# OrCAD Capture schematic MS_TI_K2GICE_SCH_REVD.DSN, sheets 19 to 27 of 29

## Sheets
19 P19_K2G_ICE_LCD_JTAG: size C; title: OLED_JTAG
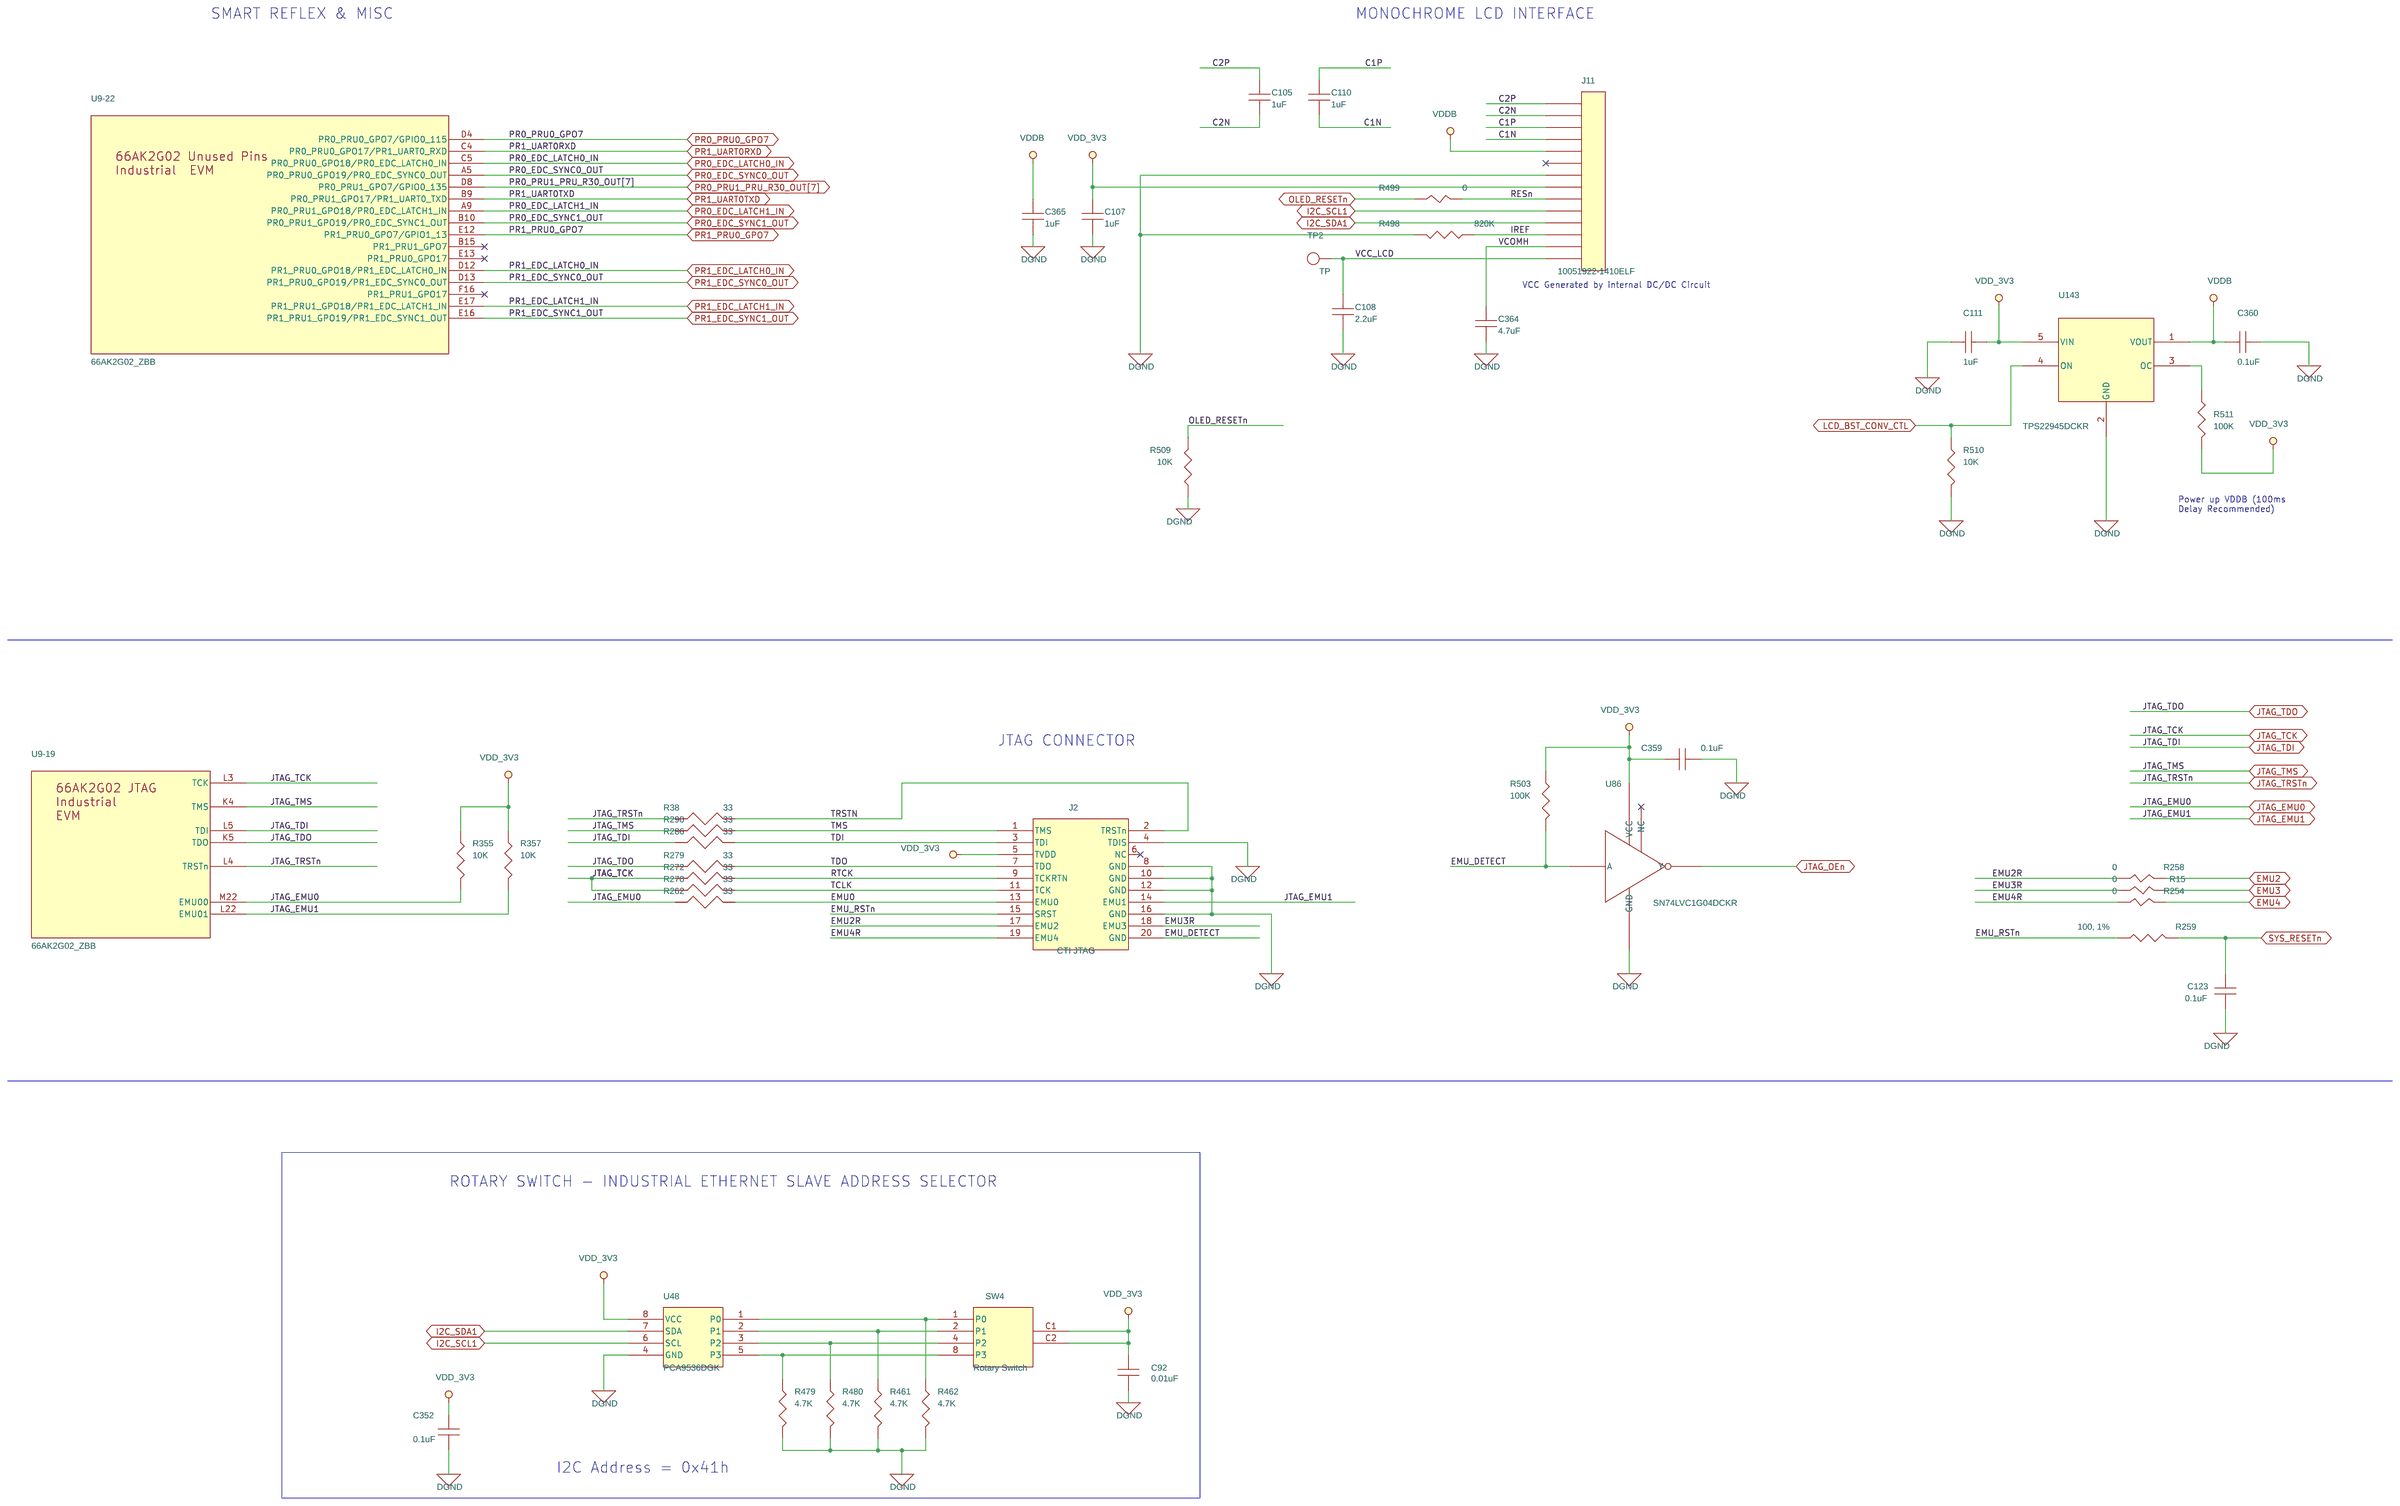
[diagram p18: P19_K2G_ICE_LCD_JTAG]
20 P20_K2G_ICE_INDUSTRIAL_LEDS: size C; title: INDUSTRIAL_LEDS
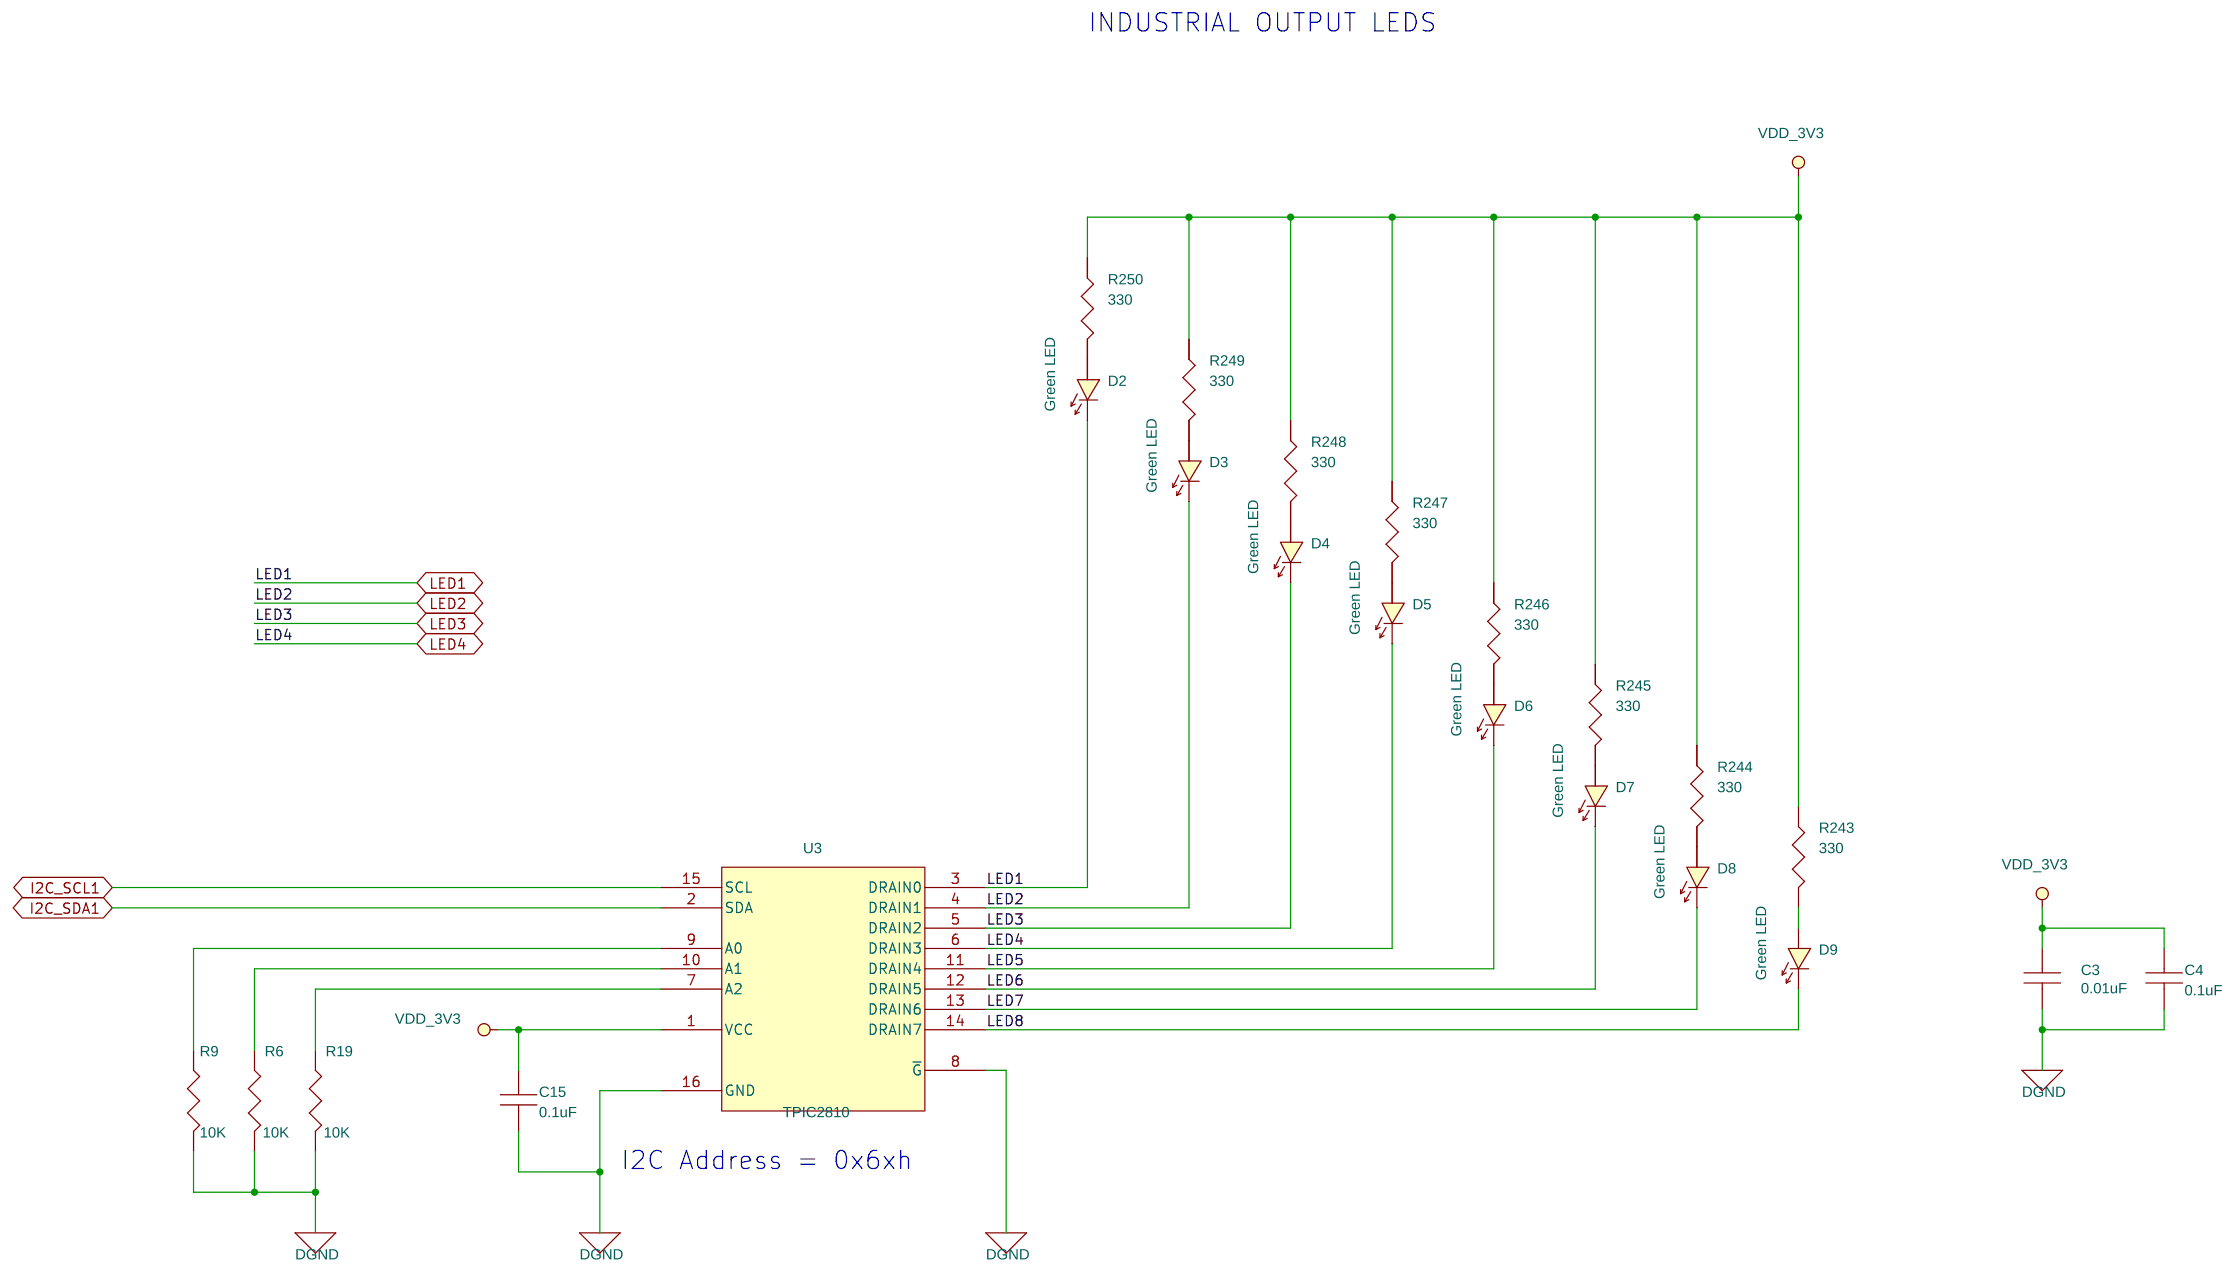
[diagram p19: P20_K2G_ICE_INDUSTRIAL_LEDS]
21 P21_USB JTAG: size C; title: USB JTAG
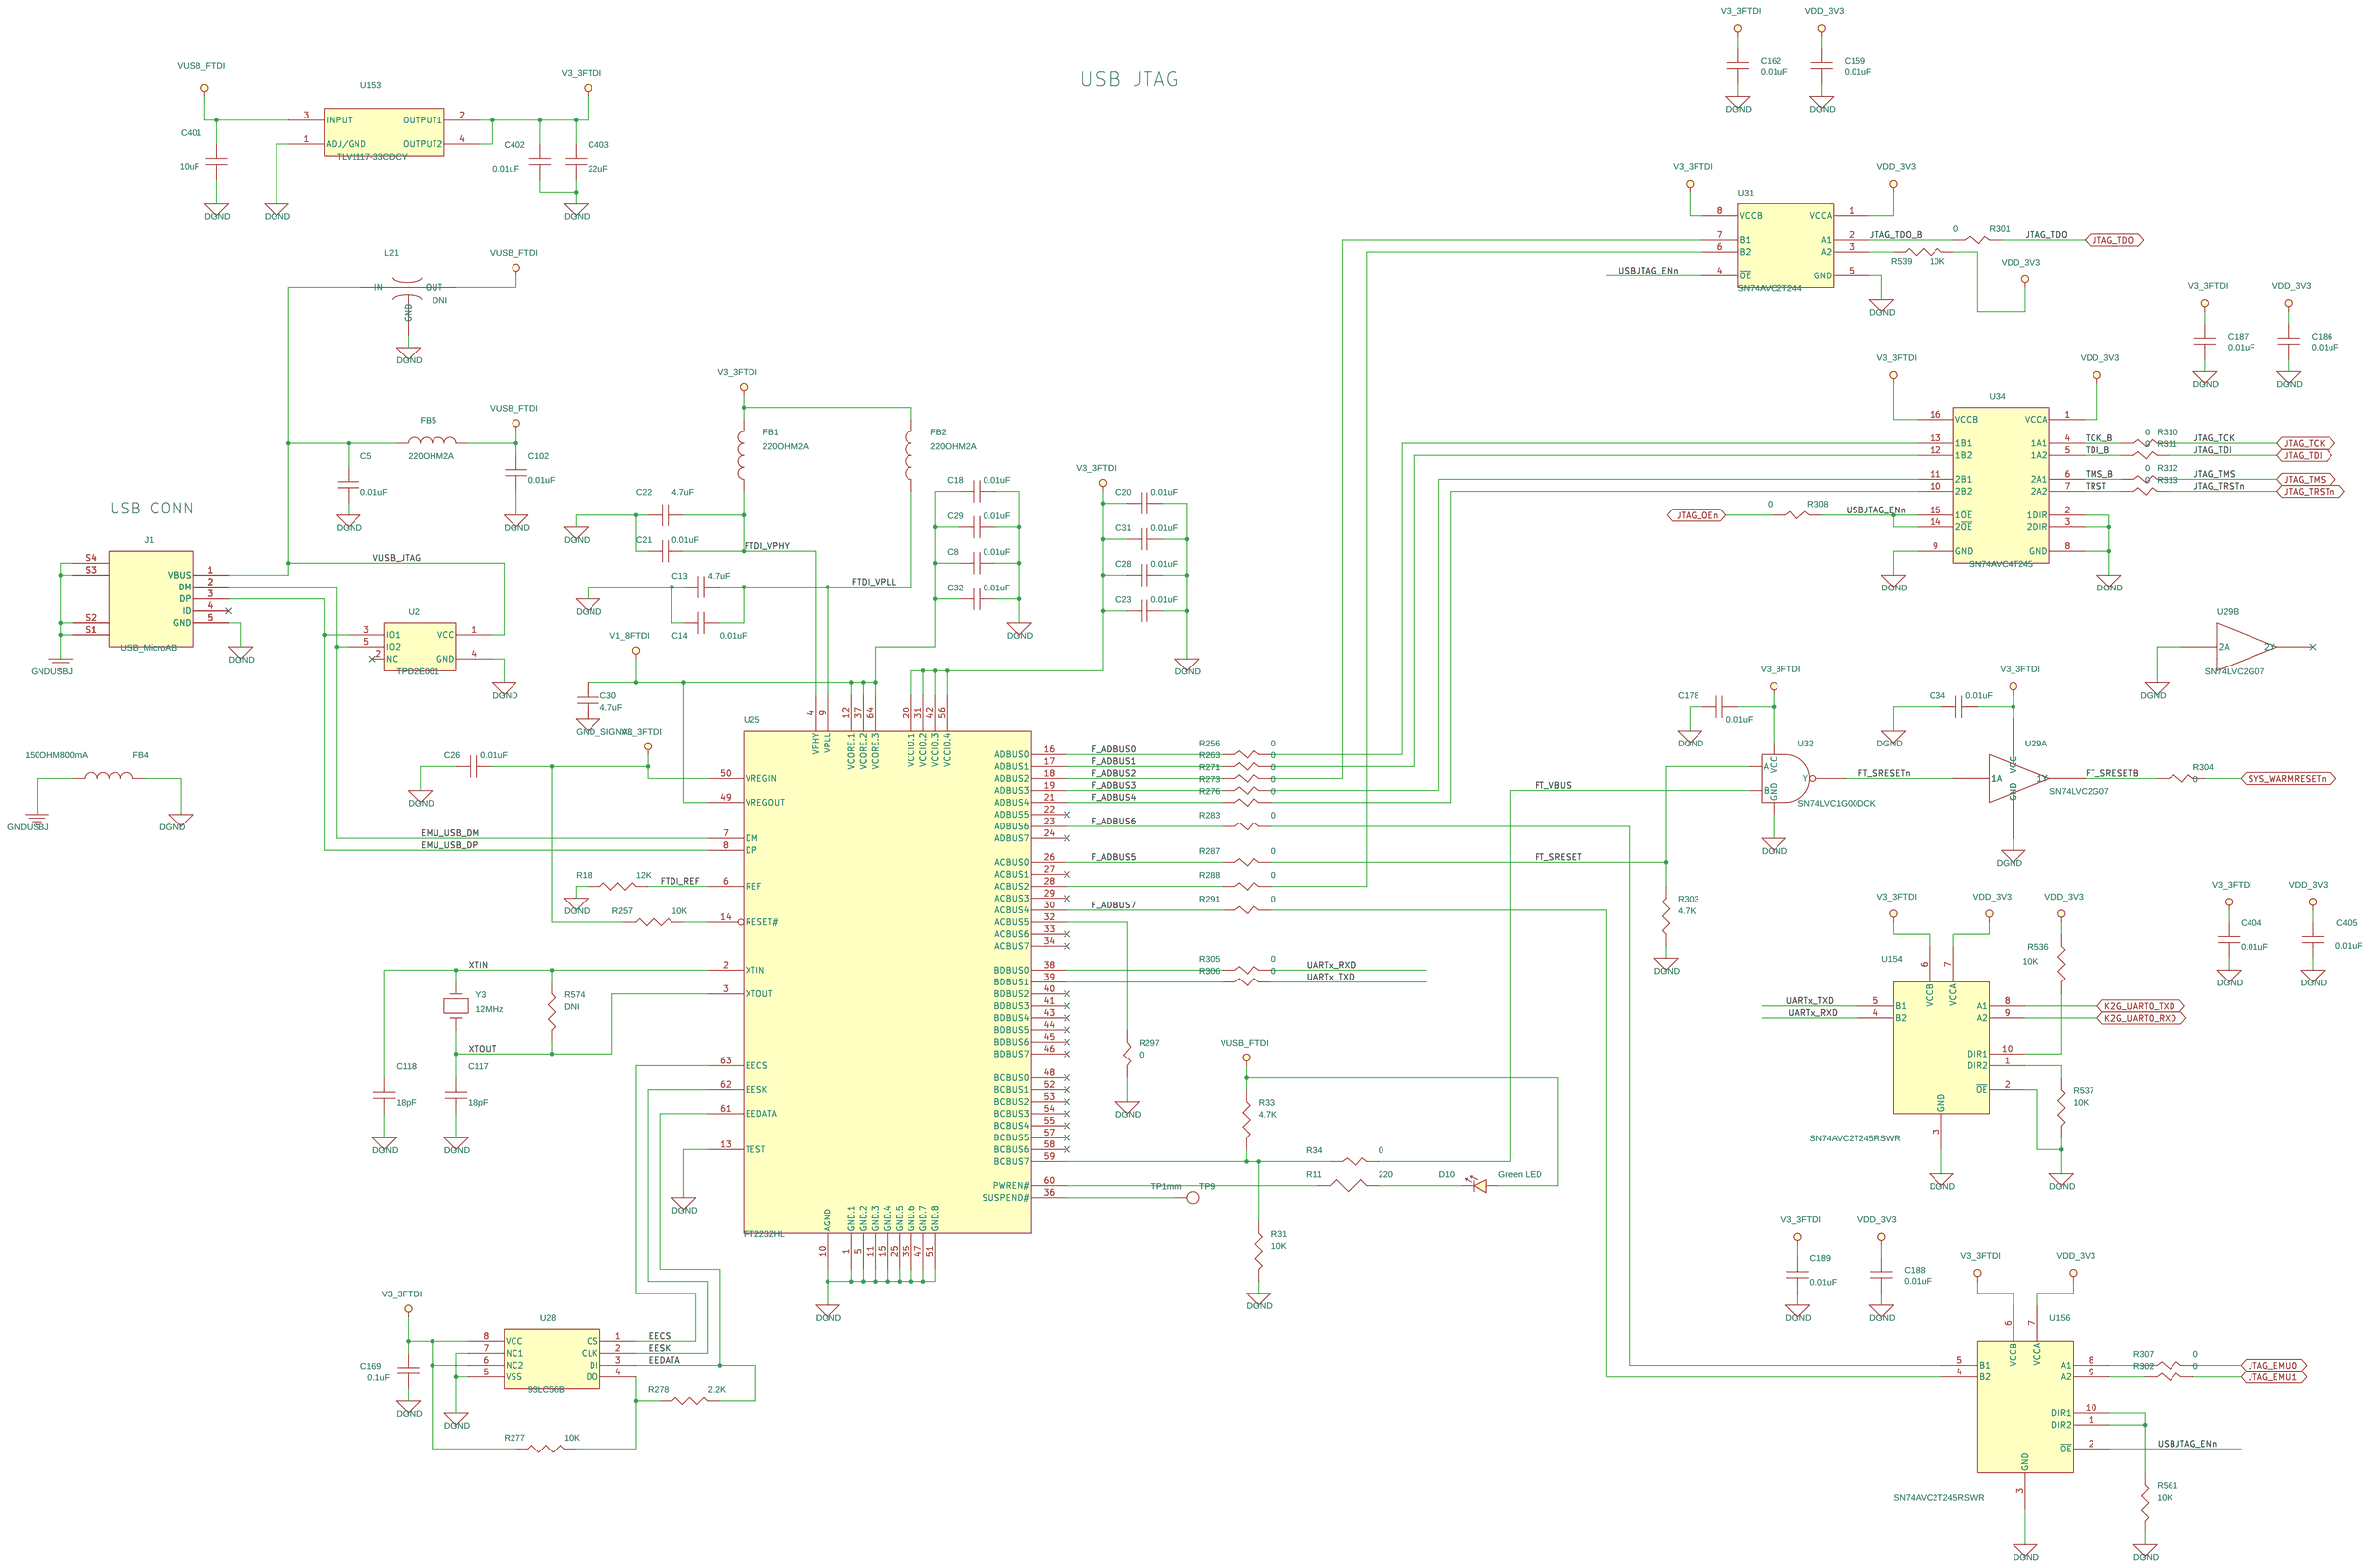
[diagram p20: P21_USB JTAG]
22 P22_MUX_DEMUX_1: size C; title: MUX_DEMUX 1
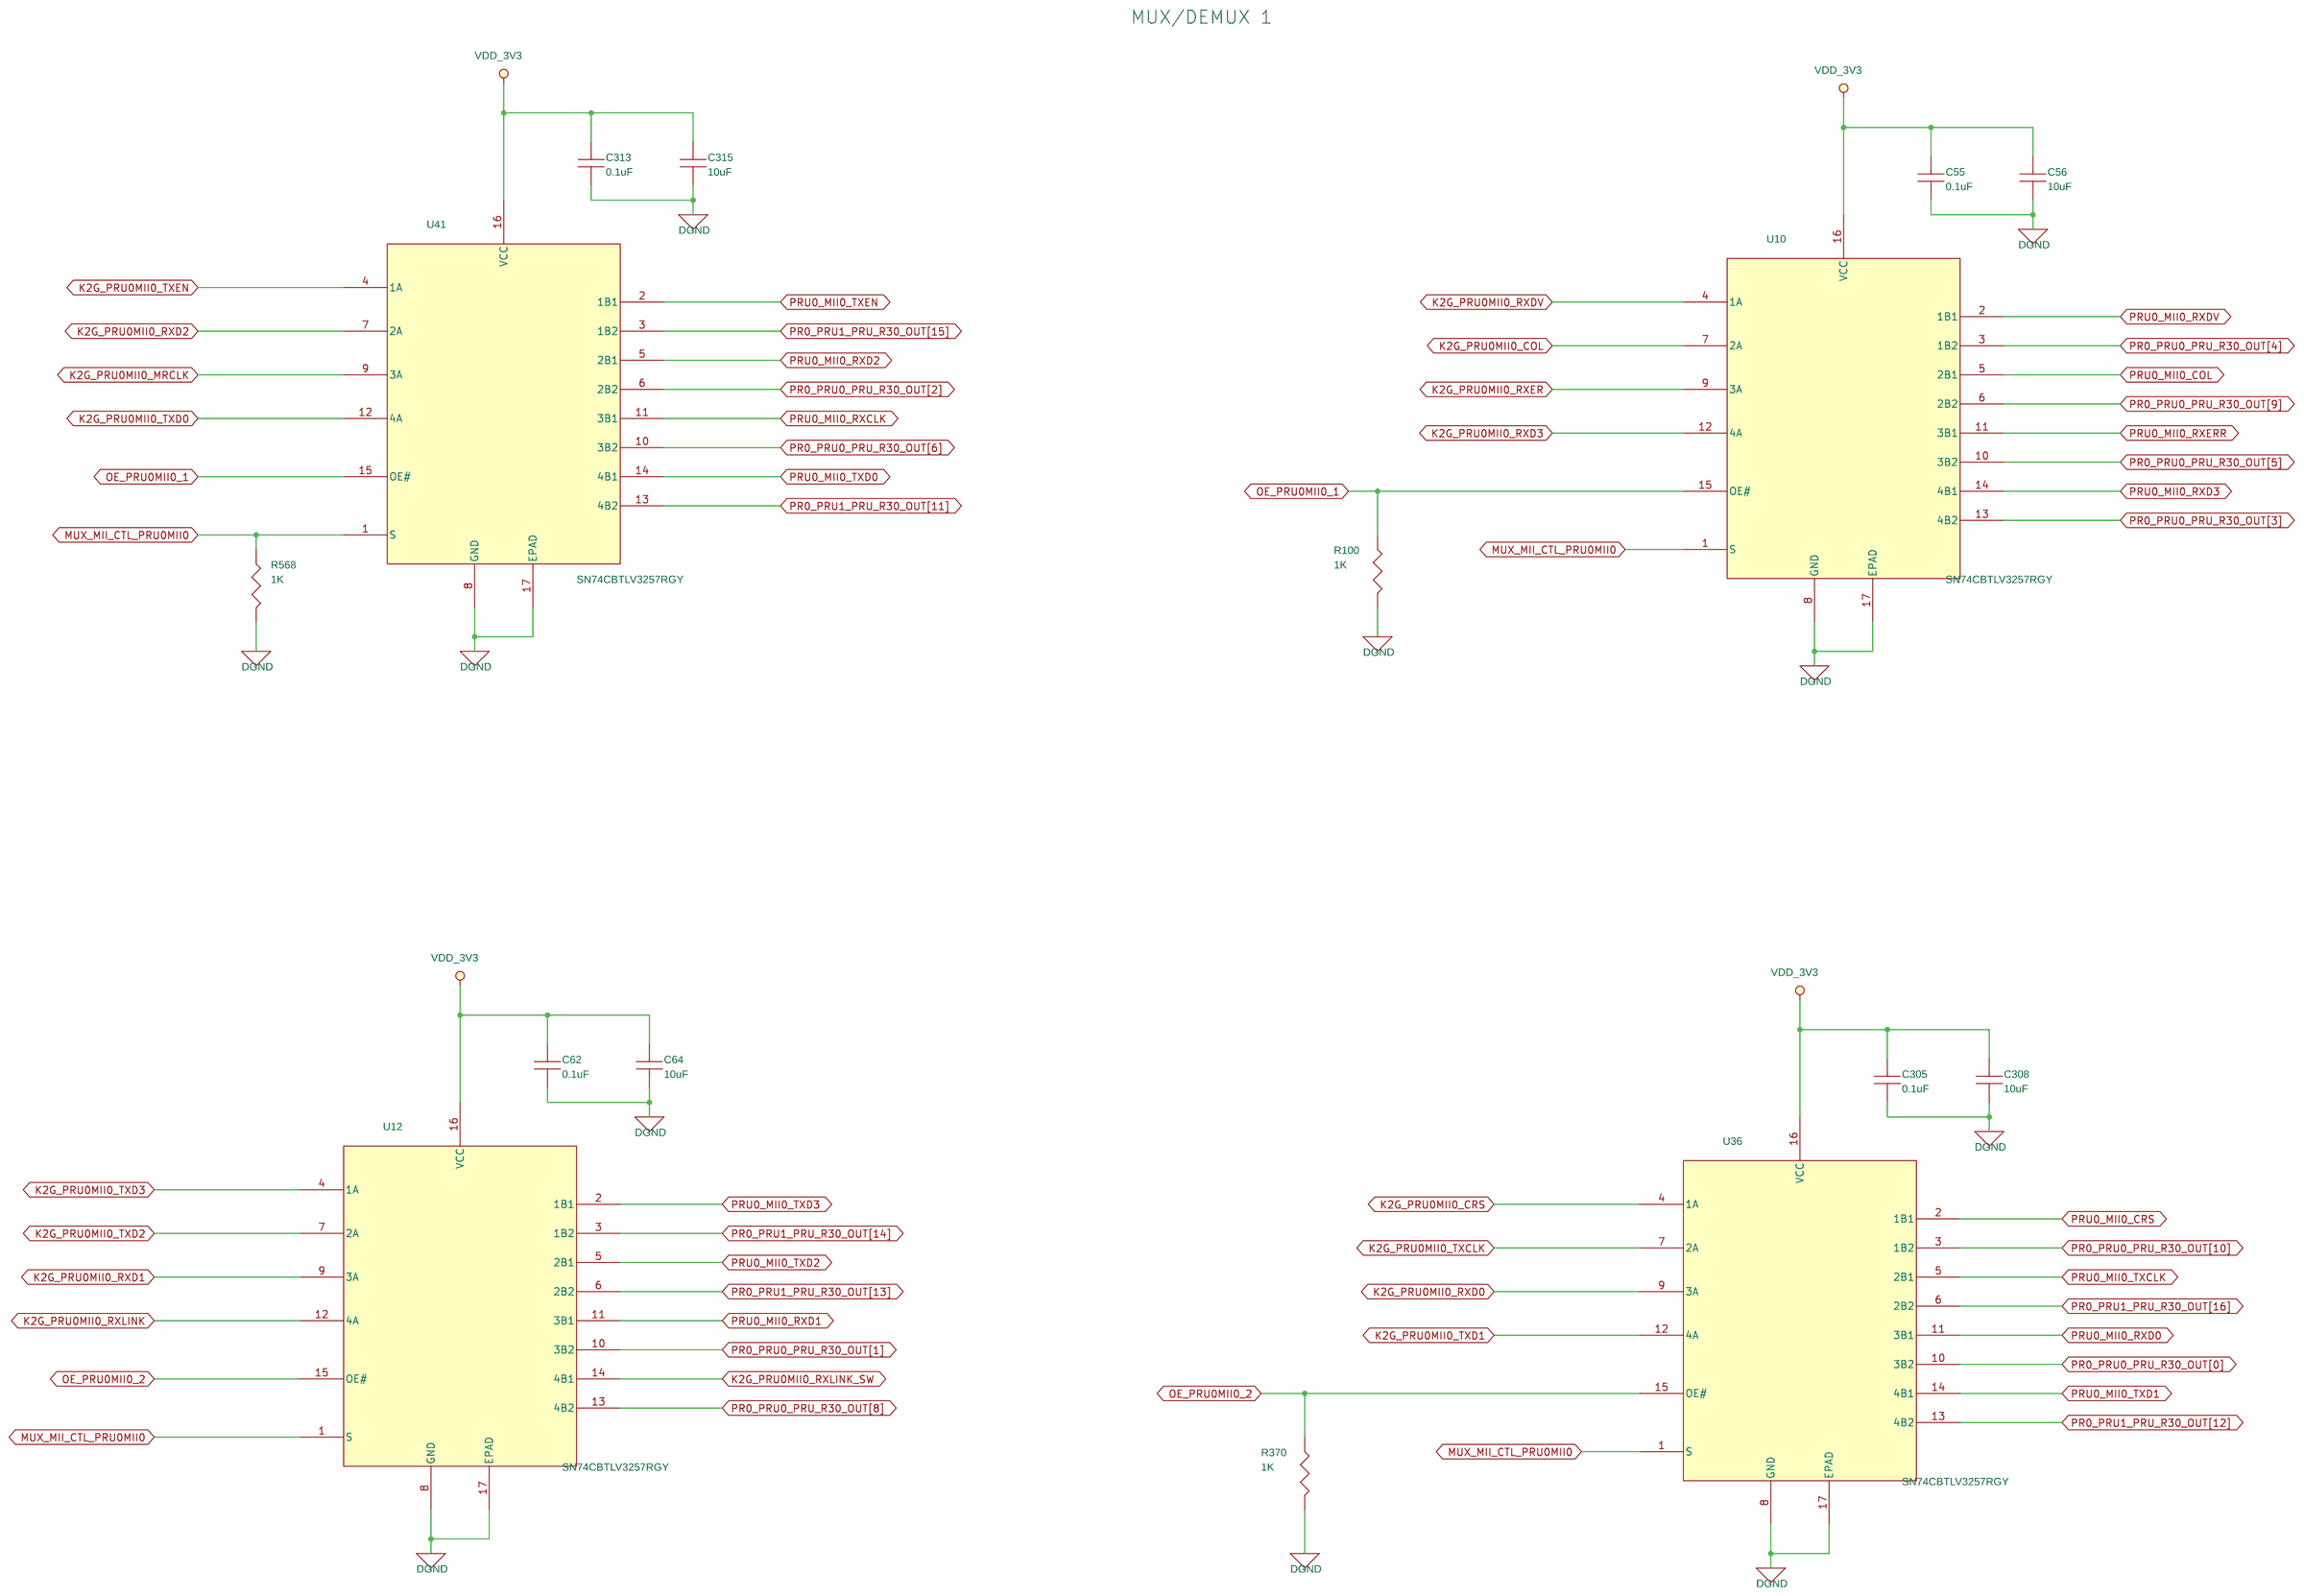
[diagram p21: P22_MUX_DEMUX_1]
23 P23_MUX_DEMUX_2: size C; title: MUX_DEMUX 2
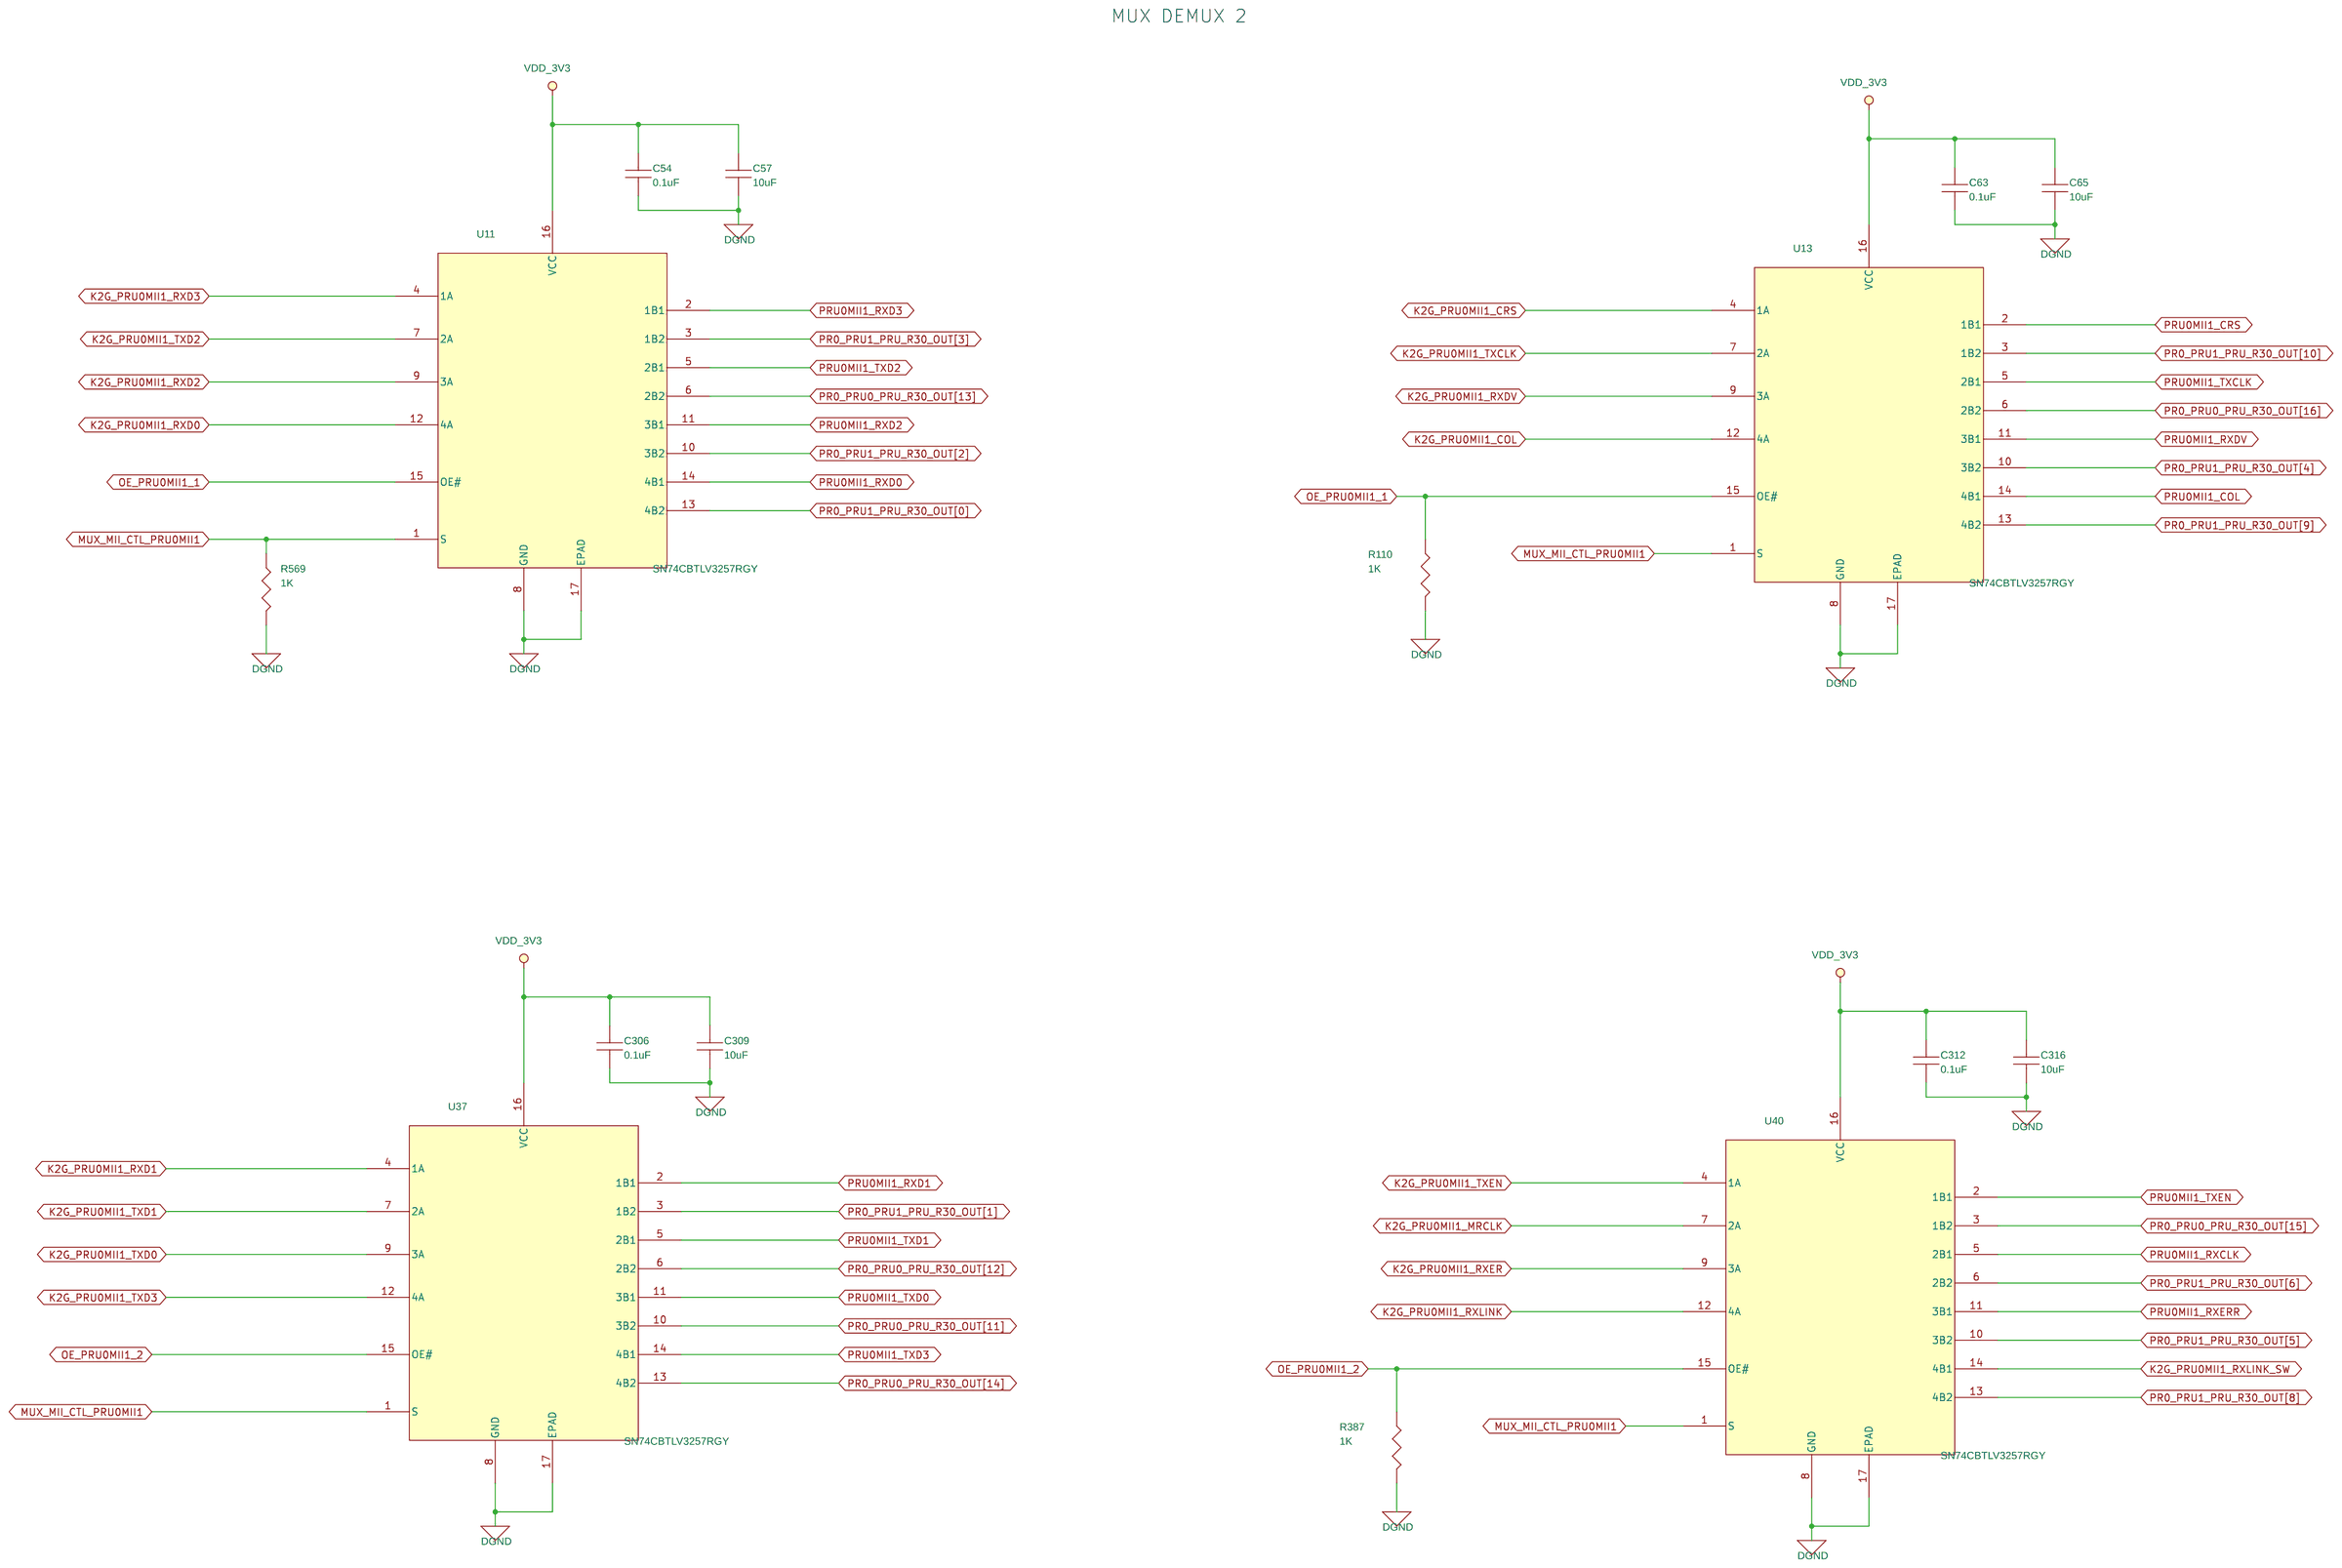
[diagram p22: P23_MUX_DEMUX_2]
24 P24_EXPANSION CONN: size C; title: EXPANSION_HEADER
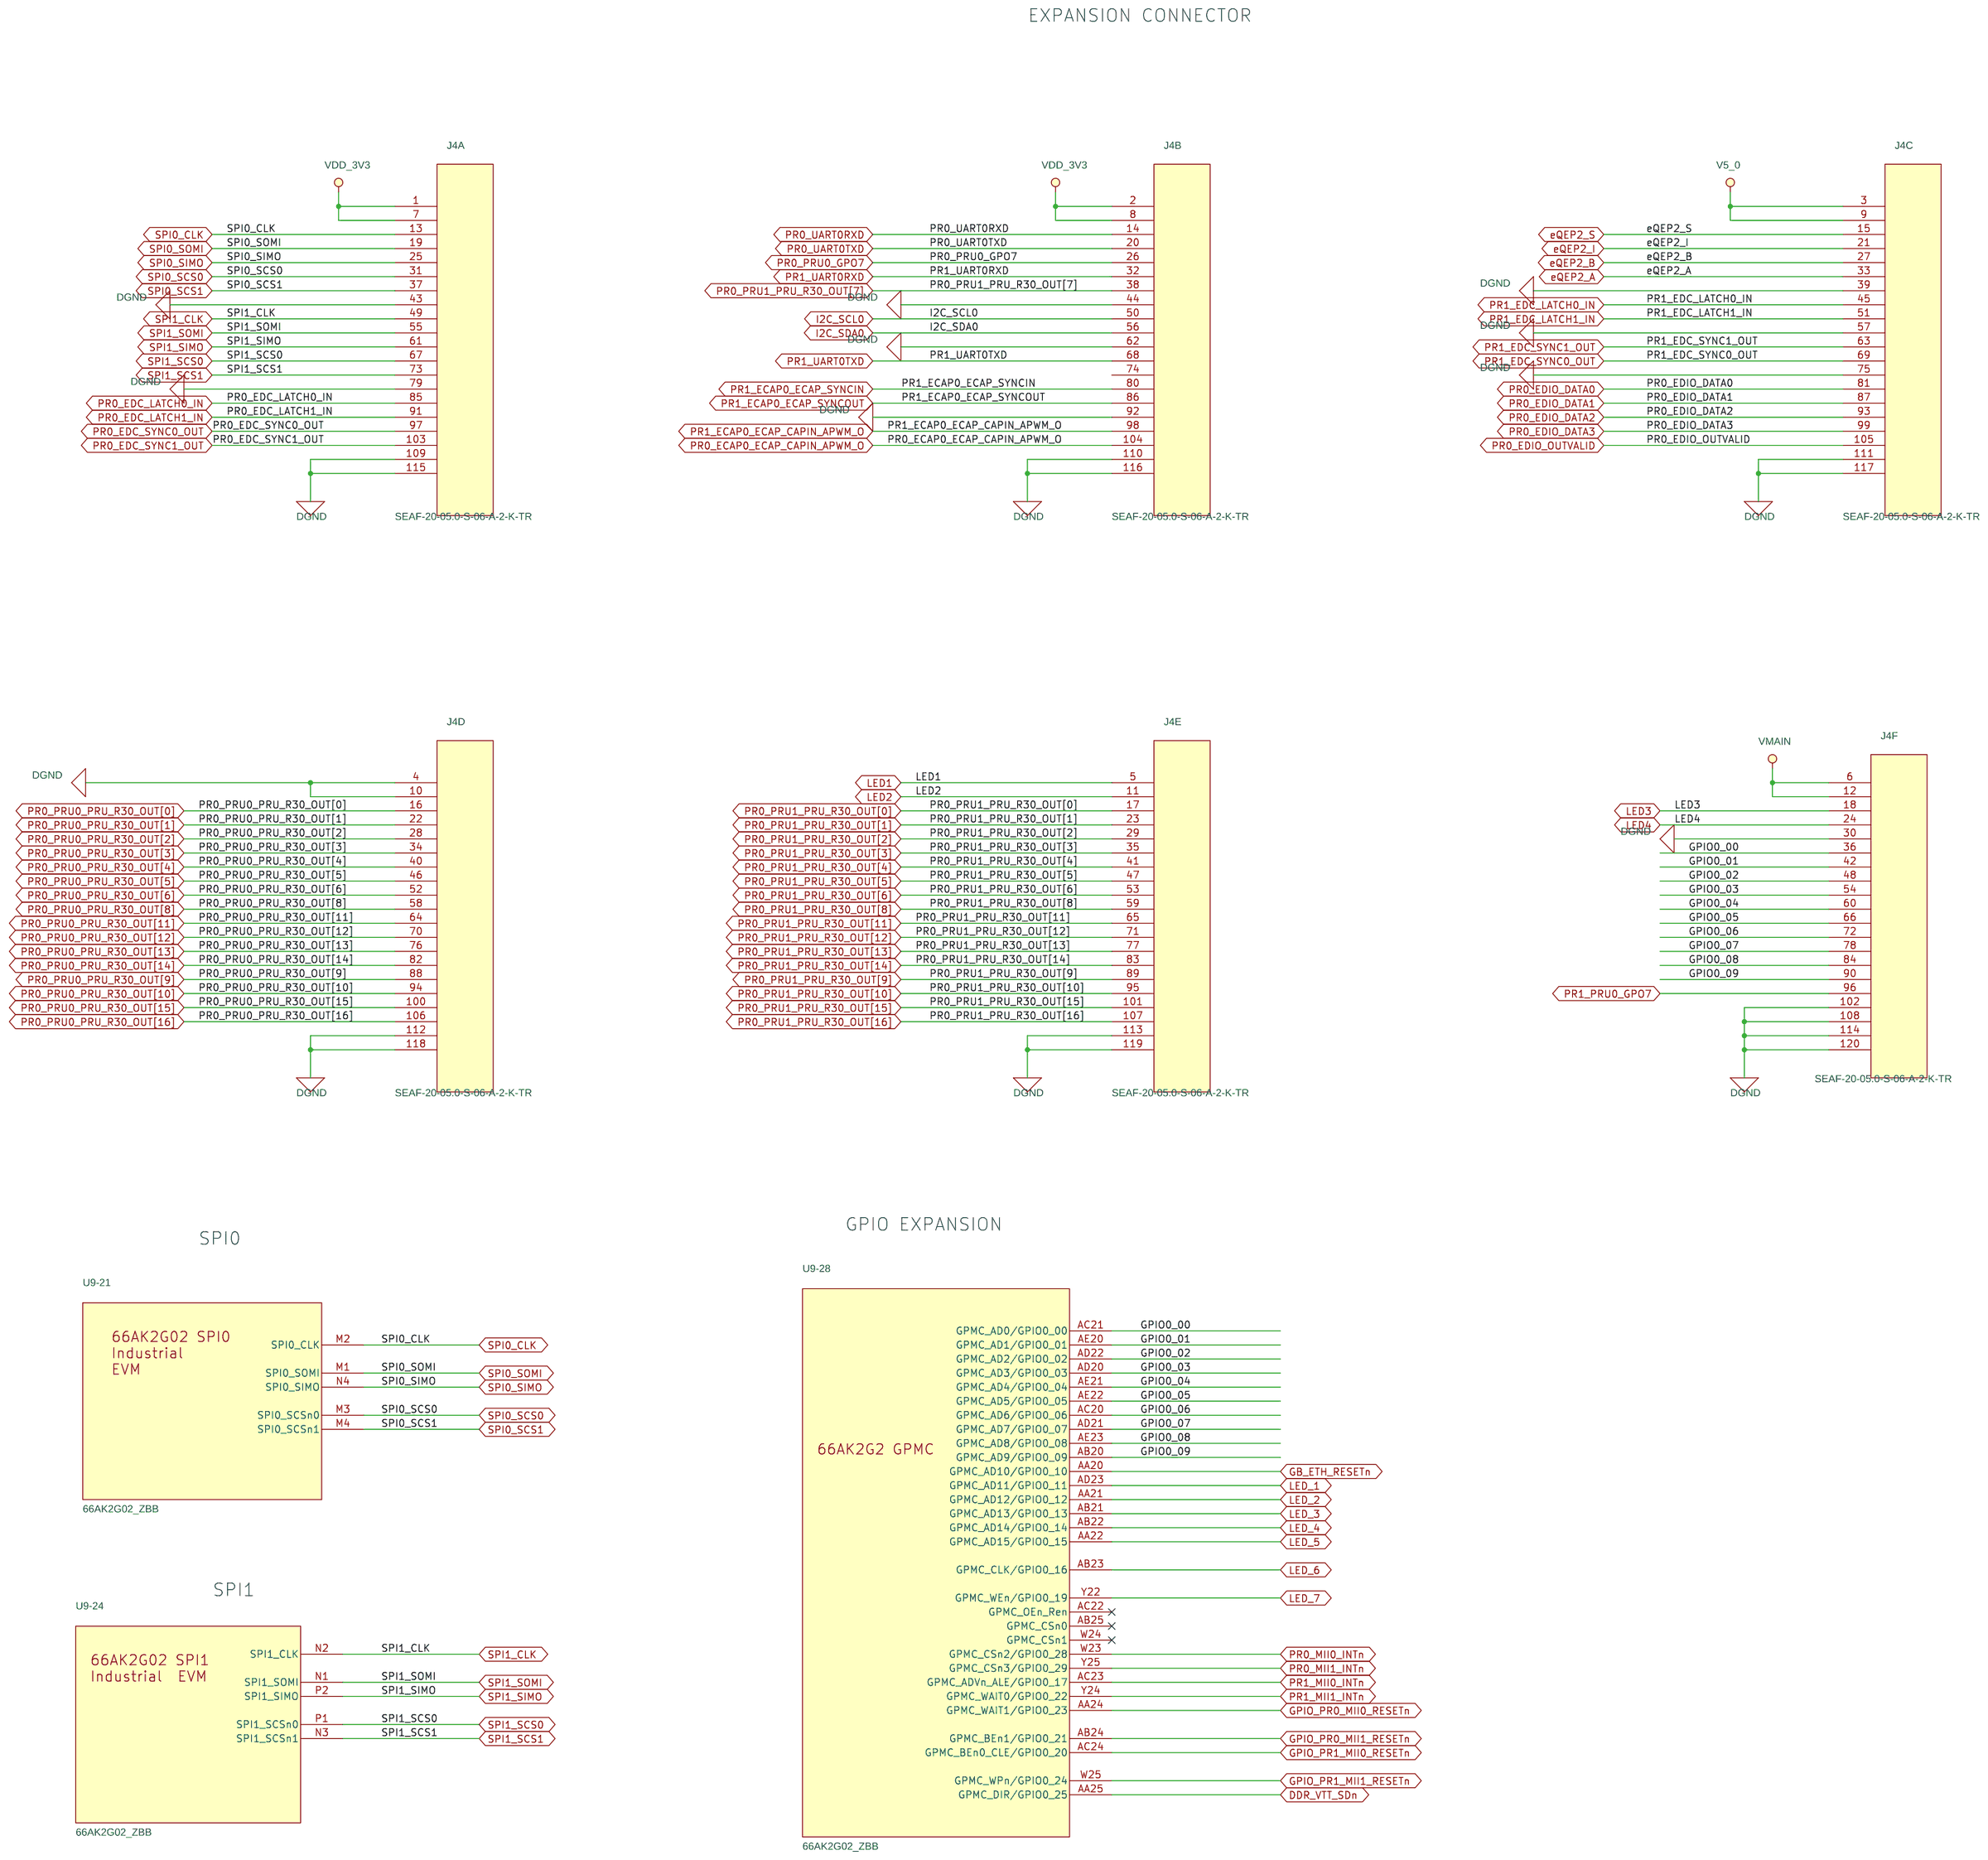
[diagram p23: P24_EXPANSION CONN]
25 P25_PCIe_CONNECTOR: size C; title: PCIe  x1 CONNECTOR
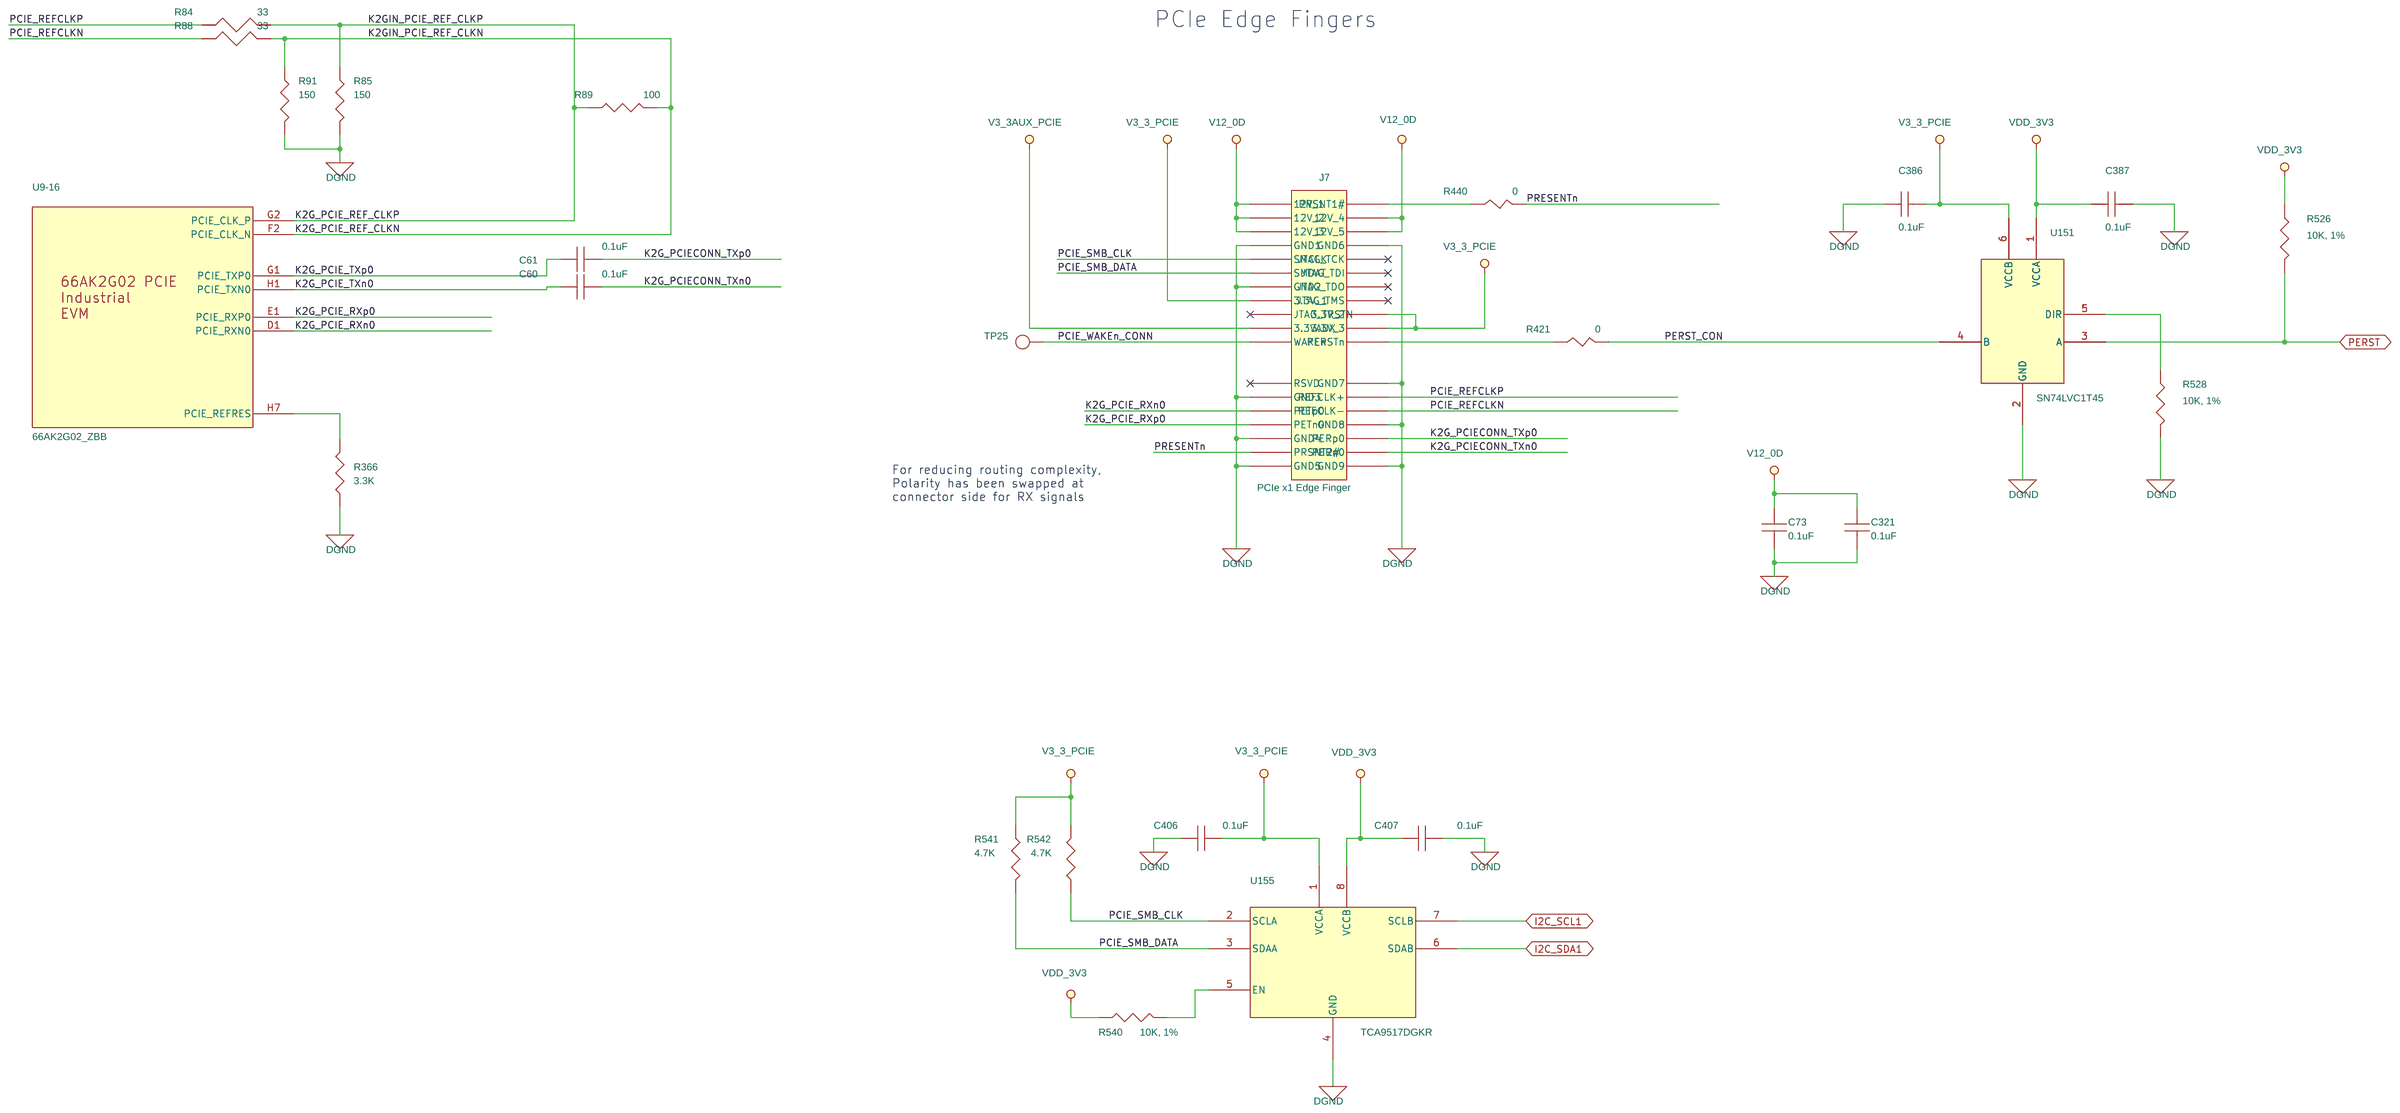
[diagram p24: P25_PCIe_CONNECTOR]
26 P26_GPIOS: size C; title: GPIOS
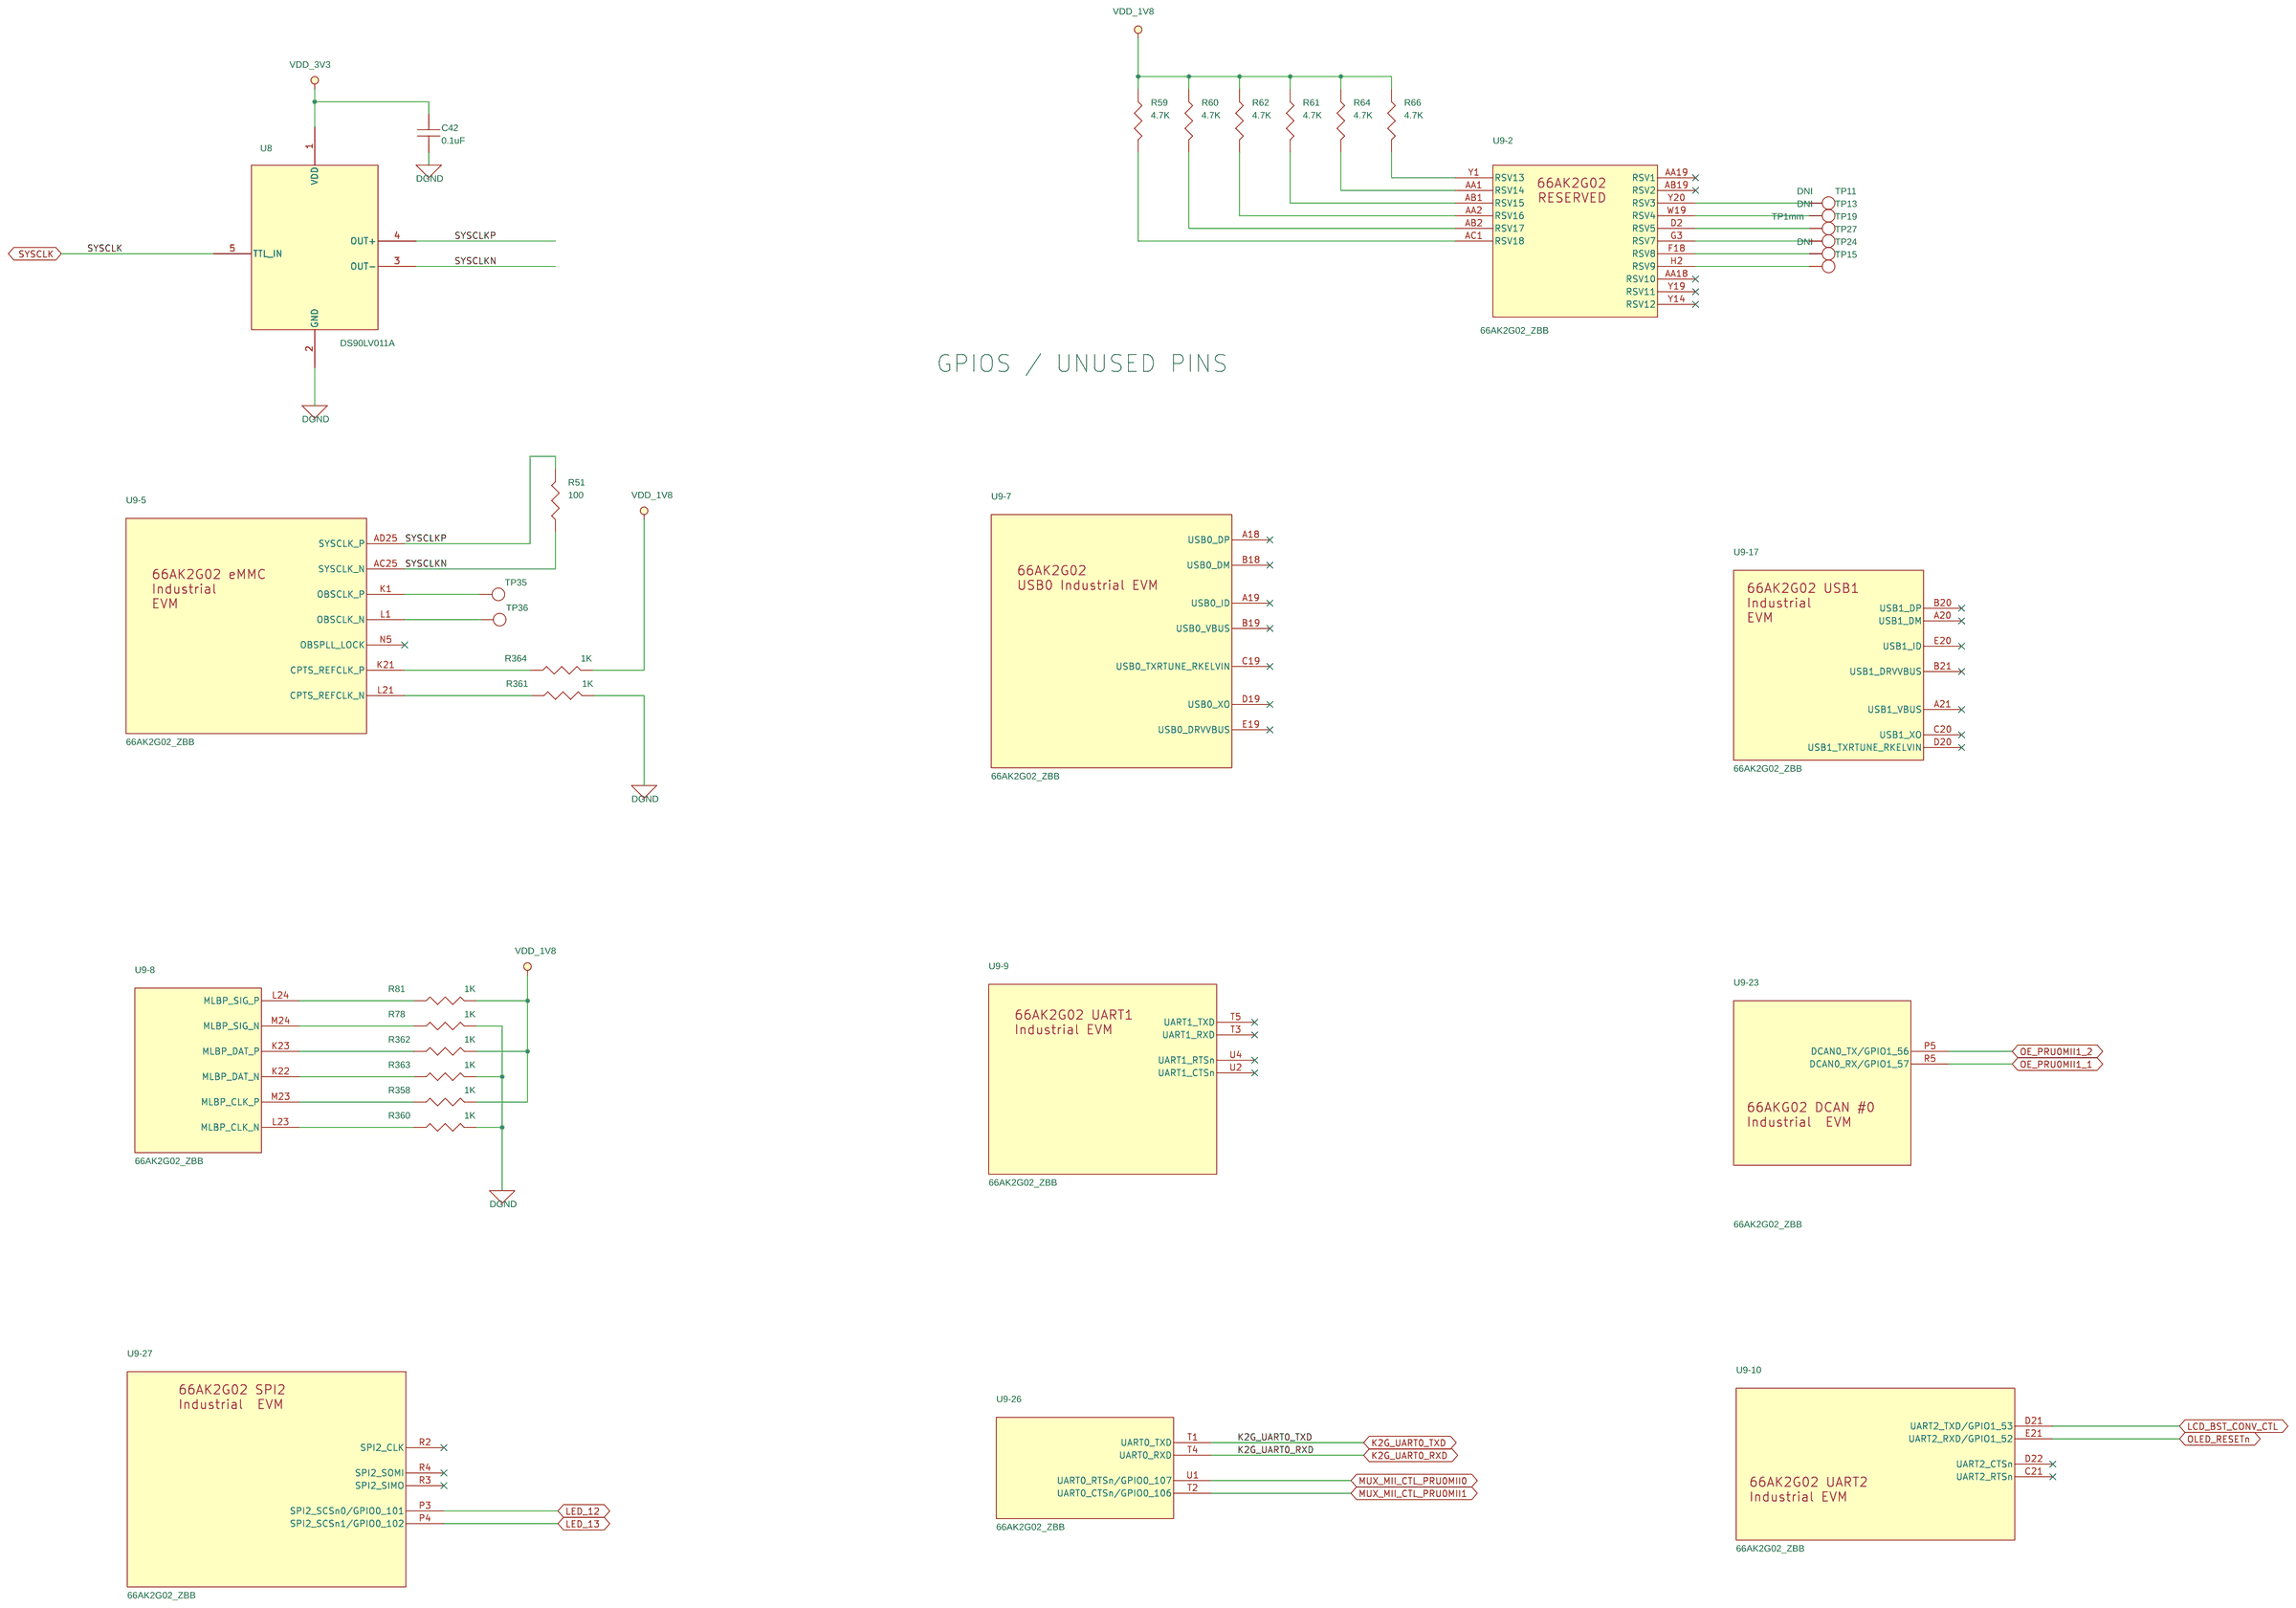
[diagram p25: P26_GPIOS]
27 P27_CURRENT MEASUREMENT: size C; title: CURRENT MEASUREMENT
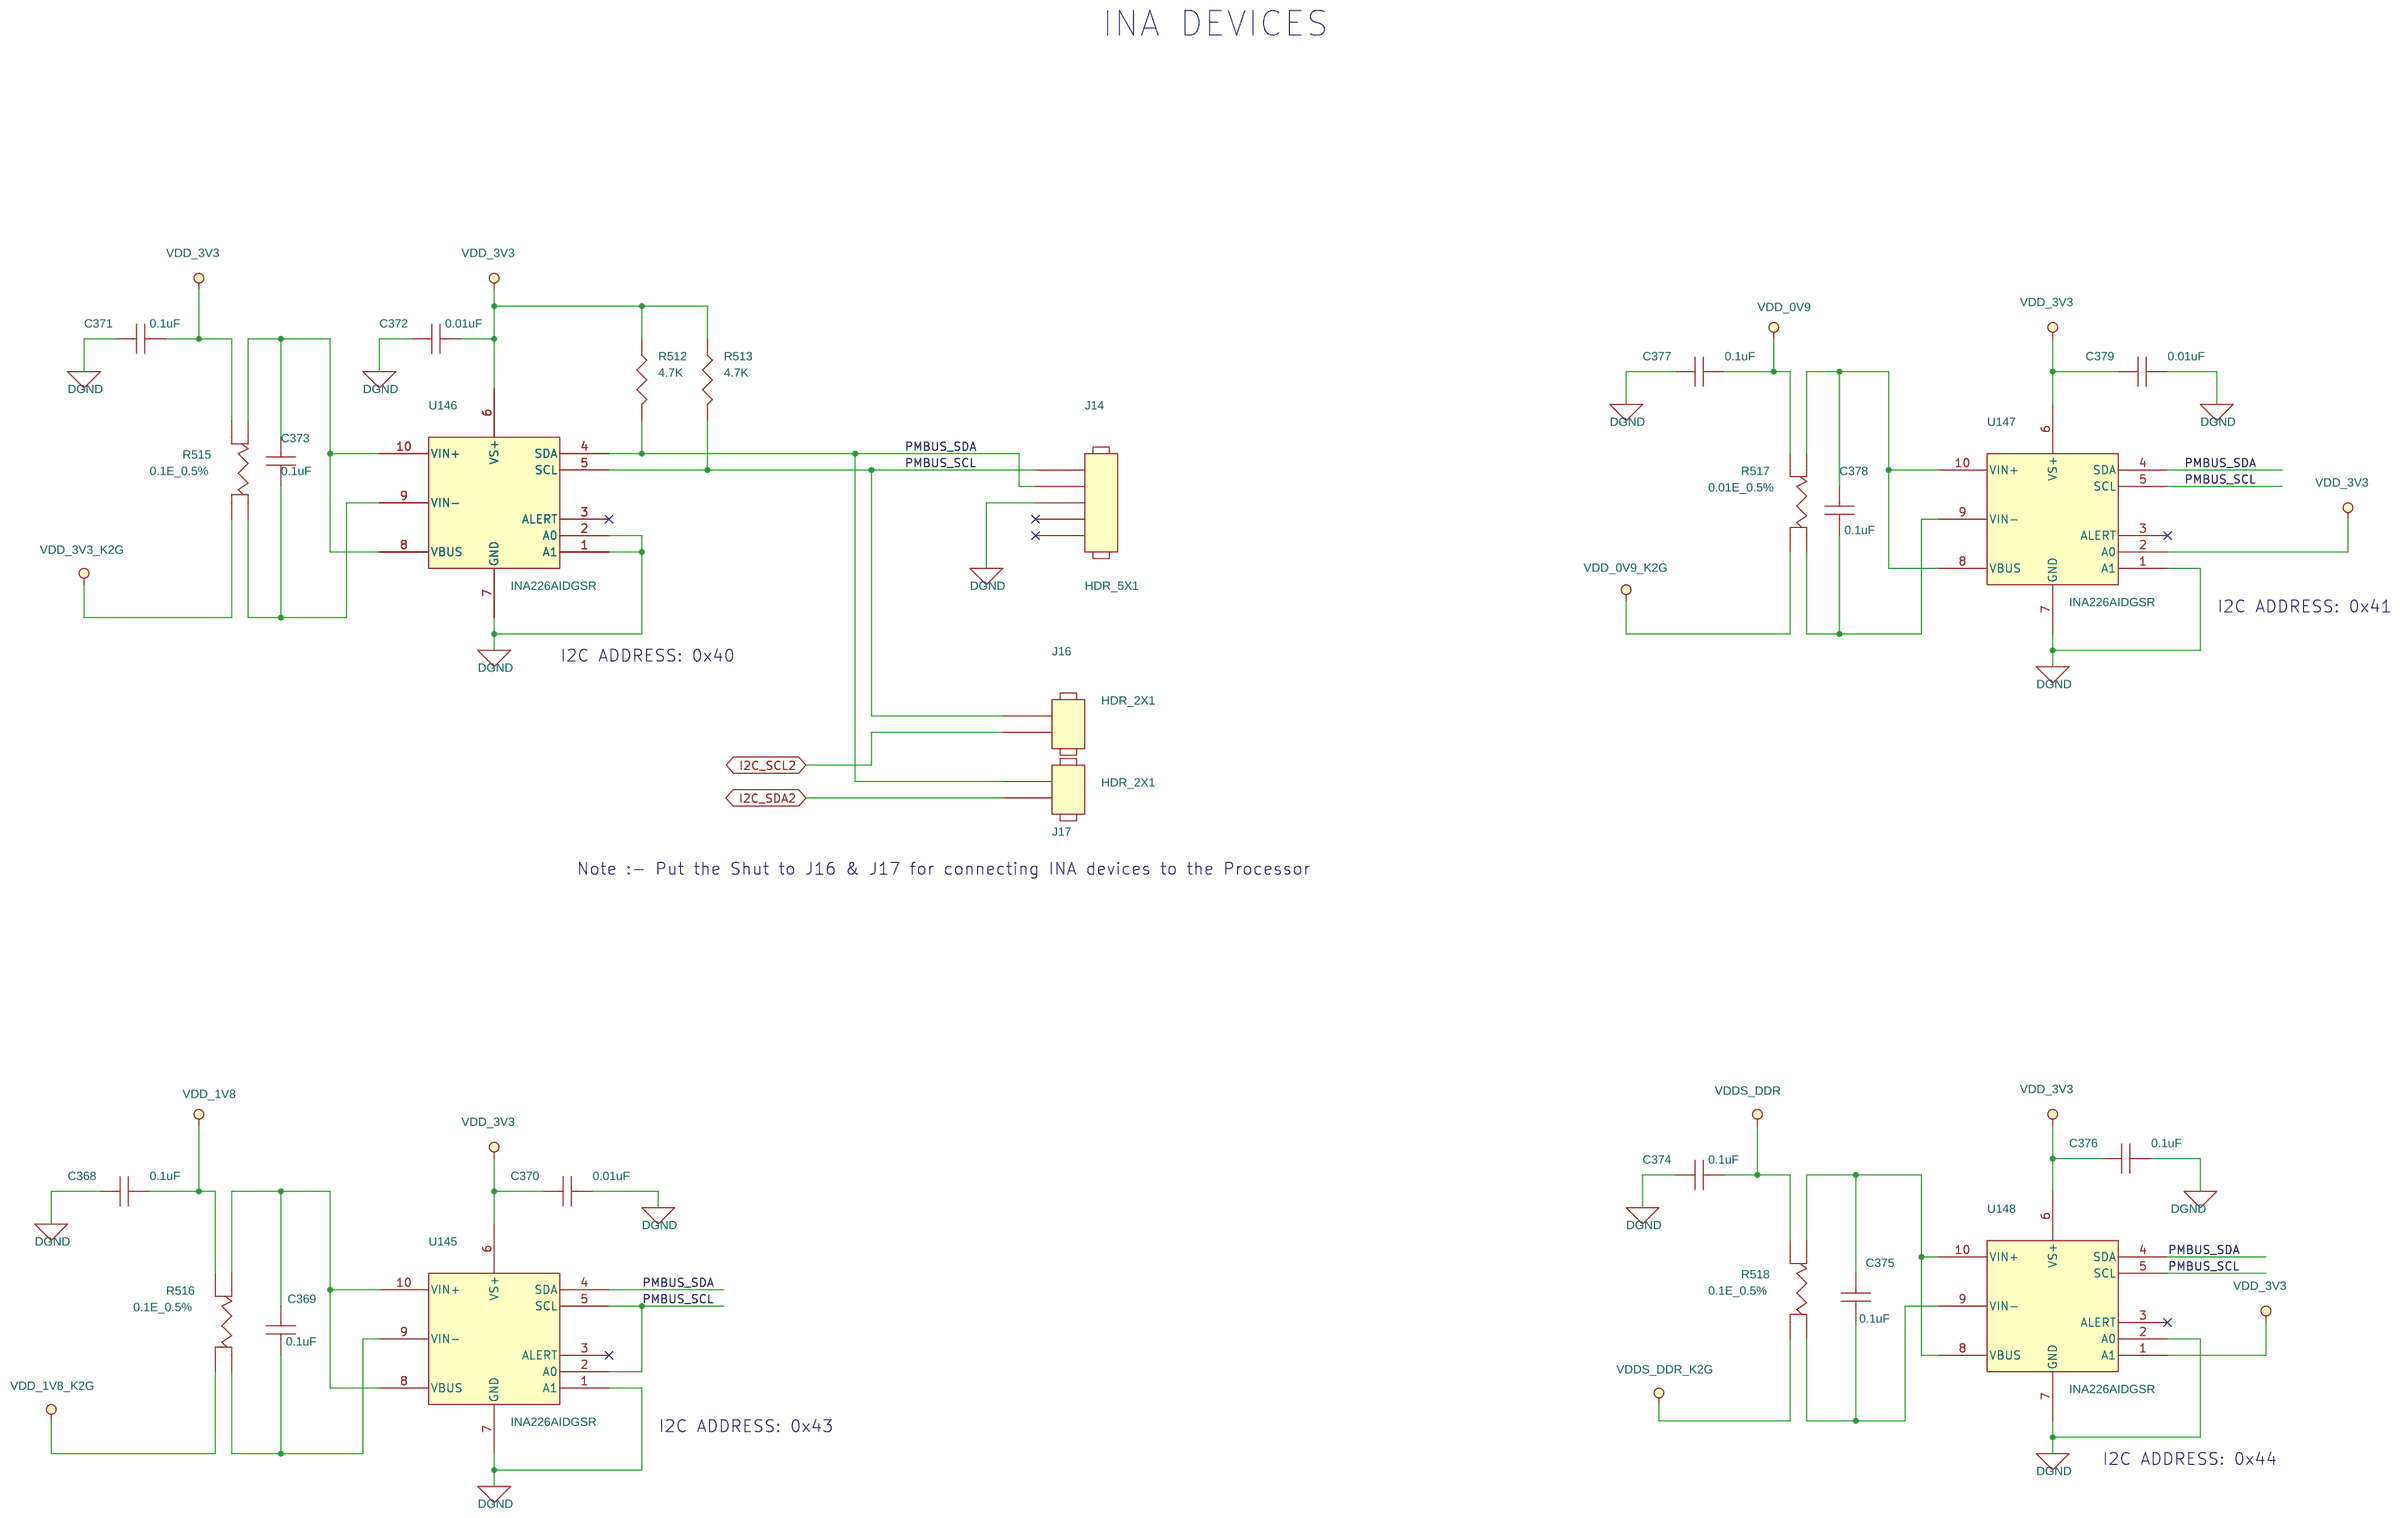
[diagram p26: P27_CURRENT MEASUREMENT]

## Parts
sheet P17_K2G_ICE_PRU1MII1_Ethernet 3
U9  66AK2G02_ZBB  [BGA21X21-625-67M]  (sections -1,-10,-11,-12,-13,-14,-15,-16,-17,-18,-19,-2,-20,-21,-22,-23,-24,-25,-26,-27,-28,-3,-4,-5,-6,-7,-8,-9)
sheet P19_K2G_ICE_LCD_JTAG
C92  0.01uF  [SM-7351-CAP-0402]
C105  1uF  [SM-7351-CAP-0402]
C107  1uF  [SM-7351-CAP-0402]
C108  2.2uF  [SM-7351-CAP-0805]
C110  1uF  [SM-7351-CAP-0402]
C111  1uF  [SM-7351-CAP-0402]
C123  0.1uF  [SM-7351-CAP-0402]
C352  0.1uF  [SM-7351-CAP-0402]
C359  0.1uF  [SM-7351-CAP-0402]
C360  0.1uF  [SM-7351-CAP-0402]
C364  4.7uF  [SM-7351-CAP-0603]
C365  1uF  [SM-7351-CAP-0402]
J2  CTI JTAG  [header10x2]
J11  10051922-1410ELF  [CON14_P5MM_3P75X9P5SMD]
R15  0  [SM-7351-RES-0402]
R38  33  [SM-7351-RES-0402]
R254  0  [SM-7351-RES-0402]
R258  0  [SM-7351-RES-0402]
R259  100, 1%  [SM-7351-RES-0402]
R262  33  [SM-7351-RES-0402]
R270  33  [SM-7351-RES-0402]
R272  33  [SM-7351-RES-0402]
R279  33  [SM-7351-RES-0402]
R286  33  [SM-7351-RES-0402]
R290  33  [SM-7351-RES-0402]
R355  10K  [SM-7351-RES-0402]
R357  10K  [SM-7351-RES-0402]
R461  4.7K  [SM-7351-RES-0402]
R462  4.7K  [SM-7351-RES-0402]
R479  4.7K  [SM-7351-RES-0402]
R480  4.7K  [SM-7351-RES-0402]
R498  820K  [SM-7351-RES-0402]
R499  0  [SM-7351-RES-0402]
R503  100K  [SM-7351-RES-0402]
R509  10K  [SM-7351-RES-0402]
R510  10K  [SM-7351-RES-0402]
R511  100K  [SM-7351-RES-0402]
SW4  Rotary Switch  [SW-ND3FR10]
TP2  TP  [TH_TP_5002]
U48  PCA9536DGK  [MSOP3X3-8-43M]
U86  SN74LVC1G04DCKR  [SC70-5]
U143  TPS22945DCKR  [SC70-5]
sheet P20_K2G_ICE_INDUSTRIAL_LEDS
C3  0.01uF  [SM-7351-CAP-0402]
C4  0.1uF  [SM-7351-CAP-0402]
C15  0.1uF  [SM-7351-CAP-0402]
D2  Green LED  [sm_led_0805]
D3  Green LED  [sm_led_0805]
D4  Green LED  [sm_led_0805]
D5  Green LED  [sm_led_0805]
D6  Green LED  [sm_led_0805]
D7  Green LED  [sm_led_0805]
D8  Green LED  [sm_led_0805]
D9  Green LED  [sm_led_0805]
R6  10K  [SM-7351-RES-0402]
R9  10K  [SM-7351-RES-0402]
R19  10K  [SM-7351-RES-0402]
R243  330  [SM-7351-RES-0402]
R244  330  [SM-7351-RES-0402]
R245  330  [SM-7351-RES-0402]
R246  330  [SM-7351-RES-0402]
R247  330  [SM-7351-RES-0402]
R248  330  [SM-7351-RES-0402]
R249  330  [SM-7351-RES-0402]
R250  330  [SM-7351-RES-0402]
U3  TPIC2810  [u_16_d]
sheet P21_USB JTAG
C5  0.01uF  [SM-7351-CAP-0402]
C8  0.01uF  [SM-7351-CAP-0402]
C13  4.7uF  [SM-7351-CAP-0603]
C14  0.01uF  [SM-7351-CAP-0402]
C18  0.01uF  [SM-7351-CAP-0402]
C20  0.01uF  [SM-7351-CAP-0402]
C21  0.01uF  [SM-7351-CAP-0402]
C22  4.7uF  [SM-7351-CAP-0603]
C23  0.01uF  [SM-7351-CAP-0402]
C26  0.01uF  [SM-7351-CAP-0402]
C28  0.01uF  [SM-7351-CAP-0402]
C29  0.01uF  [SM-7351-CAP-0402]
C30  4.7uF  [SM-7351-CAP-0603]
C31  0.01uF  [SM-7351-CAP-0402]
C32  0.01uF  [SM-7351-CAP-0402]
C34  0.01uF  [SM-7351-CAP-0402]
C102  0.01uF  [SM-7351-CAP-0402]
C117  18pF  [SM-7351-CAP-0402]
C118  18pF  [SM-7351-CAP-0402]
C159  0.01uF  [SM-7351-CAP-0402]
C162  0.01uF  [SM-7351-CAP-0402]
C169  0.1uF  [SM-7351-CAP-0402]
C178  0.01uF  [SM-7351-CAP-0402]
C186  0.01uF  [SM-7351-CAP-0402]
C187  0.01uF  [SM-7351-CAP-0402]
C188  0.01uF  [SM-7351-CAP-0402]
C189  0.01uF  [SM-7351-CAP-0402]
C401  10uF  [SM-7351-CAP-0805]
C402  0.01uF  [SM-7351-CAP-0402]
C403  22uF  [SM-7351-CAP-0805]
C404  0.01uF  [SM-7351-CAP-0402]
C405  0.01uF  [SM-7351-CAP-0402]
D10  Green LED  [sm_led_0805]
FB1  220OHM2A  [sm-7351-ind-0603]
FB2  220OHM2A  [sm-7351-ind-0603]
FB4  150OHM800mA  [sm-7351-ind-0805]
FB5  220OHM2A  [sm-7351-ind-0603]
J1  USB_MicroAB  [ZX62-AB-5PA]
L21  DNI  [FILT-NFM21PC]
R11  220  [SM-7351-RES-0402]
R18  12K  [SM-7351-RES-0402]
R31  10K  [SM-7351-RES-0402]
R33  4.7K  [SM-7351-RES-0402]
R34  0  [SM-7351-RES-0402]
R256  0  [SM-7351-RES-0402]
R257  10K  [SM-7351-RES-0402]
R263  0  [SM-7351-RES-0402]
R271  0  [SM-7351-RES-0402]
R273  0  [SM-7351-RES-0402]
R276  0  [SM-7351-RES-0402]
R277  10K  [SM-7351-RES-0402]
R278  2.2K  [sm-7351-res-0402]
R283  0  [SM-7351-RES-0402]
R287  0  [SM-7351-RES-0402]
R288  0  [SM-7351-RES-0402]
R291  0  [SM-7351-RES-0402]
R297  0  [SM-7351-RES-0402]
R301  0  [SM-7351-RES-0402]
R302  0  [SM-7351-RES-0402]
R303  4.7K  [SM-7351-RES-0402]
R304  0  [SM-7351-RES-0402]
R305  0  [SM-7351-RES-0402]
R306  0  [SM-7351-RES-0402]
R307  0  [SM-7351-RES-0402]
R308  0  [SM-7351-RES-0402]
R310  0  [SM-7351-RES-0402]
R311  0  [SM-7351-RES-0402]
R312  0  [SM-7351-RES-0402]
R313  0  [SM-7351-RES-0402]
R536  10K  [SM-7351-RES-0402]
R537  10K  [SM-7351-RES-0402]
R539  10K  [SM-7351-RES-0402]
R561  10K  [SM-7351-RES-0402]
R574  DNI  [SM-7351-RES-0402]
TP9  TP1mm  [tp_smd1mmcircle]
U2  TPD2E001  [U_5_DRL]
U25  FT2232HL  [LQFP64pin]
U28  93LC56B  [SOIC8_MC]
U29  SN74LVC2G07  [U_6_DCK]  (sections A,B)
U31  SN74AVC2T244  [son2x1-8-16m]
U32  SN74LVC1G00DCK  [SC70-5-43M]
U34  SN74AVC4T245  [U_16_PW]
U153  TLV1117-33CDCY  [SOT223-4]
U154  SN74AVC2T245RSWR  [QFN10_15-74_75X60]
U156  SN74AVC2T245RSWR  [QFN10_15-74_75X60]
Y3  12MHz  [SM_OSC_ABM3]
sheet P22_MUX_DEMUX_1
C55  0.1uF  [SM-7351-CAP-0402]
C56  10uF  [SM-7351-CAP-0805]
C62  0.1uF  [SM-7351-CAP-0402]
C64  10uF  [SM-7351-CAP-0805]
C305  0.1uF  [SM-7351-CAP-0402]
C308  10uF  [SM-7351-CAP-0805]
C313  0.1uF  [SM-7351-CAP-0402]
C315  10uF  [SM-7351-CAP-0805]
R100  1K  [SM-7351-RES-0402]
R370  1K  [SM-7351-RES-0402]
R568  1K  [SM-7351-RES-0402]
U10  SN74CBTLV3257RGY  [QFN4X3P5-16-39M]
U12  SN74CBTLV3257RGY  [QFN4X3P5-16-39M]
U36  SN74CBTLV3257RGY  [QFN4X3P5-16-39M]
U41  SN74CBTLV3257RGY  [QFN4X3P5-16-39M]
sheet P23_MUX_DEMUX_2
C54  0.1uF  [SM-7351-CAP-0402]
C57  10uF  [SM-7351-CAP-0805]
C63  0.1uF  [SM-7351-CAP-0402]
C65  10uF  [SM-7351-CAP-0805]
C306  0.1uF  [SM-7351-CAP-0402]
C309  10uF  [SM-7351-CAP-0805]
C312  0.1uF  [SM-7351-CAP-0402]
C316  10uF  [SM-7351-CAP-0805]
R110  1K  [SM-7351-RES-0402]
R387  1K  [SM-7351-RES-0402]
R569  1K  [SM-7351-RES-0402]
U11  SN74CBTLV3257RGY  [QFN4X3P5-16-39M]
U13  SN74CBTLV3257RGY  [QFN4X3P5-16-39M]
U37  SN74CBTLV3257RGY  [QFN4X3P5-16-39M]
U40  SN74CBTLV3257RGY  [QFN4X3P5-16-39M]
sheet P24_EXPANSION CONN
J4  SEAF-20-05.0-S-06-A-2-K-TR  [CNSEAF20X6]  (sections A,B,C,D,E,F)
sheet P25_PCIe_CONNECTOR
C60  0.1uF  [SM-7351-CAP-0402]
C61  0.1uF  [SM-7351-CAP-0402]
C73  0.1uF  [SM-7351-CAP-0402]
C321  0.1uF  [SM-7351-CAP-0402]
C386  0.1uF  [SM-7351-CAP-0402]
C387  0.1uF  [SM-7351-CAP-0402]
C406  0.1uF  [SM-7351-CAP-0402]
C407  0.1uF  [SM-7351-CAP-0402]
J7  PCIe x1 Edge Finger  [PCIE-X1-EDGE]
R84  33  [SM-7351-RES-0402]
R85  150  [SM-7351-RES-0402]
R88  33  [SM-7351-RES-0402]
R89  100  [SM-7351-RES-0402]
R91  150  [SM-7351-RES-0402]
R366  3.3K  [SM-7351-RES-0402]
R421  0  [SM-7351-RES-0402]
R440  0  [SM-7351-RES-0402]
R526  10K, 1%  [SM-7351-RES-0402]
R528  10K, 1%  [SM-7351-RES-0402]
R540  10K, 1%  [SM-7351-RES-0402]
R541  4.7K  [SM-7351-RES-0402]
R542  4.7K  [SM-7351-RES-0402]
TP25  TP1mm  [tp_smd1mmcircle]
U151  SN74LVC1T45  [SOT23-6]
U155  TCA9517DGKR  [VSSOP8_25-59_120X120]
sheet P26_GPIOS
C42  0.1uF  [SM-7351-CAP-0402]
R51  100  [SM-7351-RES-0402]
R59  4.7K  [SM-7351-RES-0402]
R60  4.7K  [SM-7351-RES-0402]
R61  4.7K  [SM-7351-RES-0402]
R62  4.7K  [SM-7351-RES-0402]
R64  4.7K  [SM-7351-RES-0402]
R66  4.7K  [SM-7351-RES-0402]
R78  1K  [SM-7351-RES-0402]
R81  1K  [SM-7351-RES-0402]
R358  1K  [SM-7351-RES-0402]
R360  1K  [SM-7351-RES-0402]
R361  1K  [SM-7351-RES-0402]
R362  1K  [SM-7351-RES-0402]
R363  1K  [SM-7351-RES-0402]
R364  1K  [SM-7351-RES-0402]
TP11  DNI  [TH_TP_5002]
TP13  DNI  [TH_TP_5002]
TP15  DNI  [TH_TP_5002]
TP19  TP1mm  [tp_smd1mmcircle]
TP24  DNI  [TH_TP_5002]
TP27  DNI  [TH_TP_5002]
TP35  TP1mm  [tp_smd1mmcircle]
TP36  TP1mm  [tp_smd1mmcircle]
U8  DS90LV011A  [SOT23-5-43M]
sheet P27_CURRENT MEASUREMENT
C368  0.1uF  [SM-7351-CAP-0402]
C369  0.1uF  [SM-7351-CAP-0402]
C370  0.01uF  [SM-7351-CAP-0402]
C371  0.1uF  [SM-7351-CAP-0402]
C372  0.01uF  [SM-7351-CAP-0402]
C373  0.1uF  [SM-7351-CAP-0402]
C374  0.1uF  [SM-7351-CAP-0402]
C375  0.1uF  [SM-7351-CAP-0402]
C376  0.1uF  [SM-7351-CAP-0402]
C377  0.1uF  [SM-7351-CAP-0402]
C378  0.1uF  [SM-7351-CAP-0402]
C379  0.01uF  [SM-7351-CAP-0402]
J14  HDR_5X1  [HDR_5X1_100_S_T]
J16  HDR_2X1  [HDR_2X1_100_S_T]
J17  HDR_2X1  [HDR_2X1_100_S_T]
R512  4.7K  [SM-7351-RES-0402]
R513  4.7K  [SM-7351-RES-0402]
R515  0.1E_0.5%  [RES1206-4TERM]
R516  0.1E_0.5%  [RES1206-4TERM]
R517  0.01E_0.5%  [RES1206-4TERM]
R518  0.1E_0.5%  [RES1206-4TERM]
U145  INA226AIDGSR  [MSOP10_19-68_120X120]
U146  INA226AIDGSR  [MSOP10_19-68_120X120]
U147  INA226AIDGSR  [MSOP10_19-68_120X120]
U148  INA226AIDGSR  [MSOP10_19-68_120X120]

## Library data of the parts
U9 = 66AK2G02-ZBB_BGA625: Crtd /date: VASANTHA/090616; DescriptiveText: IC ARM CORTEX AND DSP 32 BIT MICROPROCESSOR BGA625; Mfr: TEXAS INSTRUMENTS; Mistral part number: NSPN00330; Part_type: ICS\DIGITAL\MICROPROCESSOR
C3 C5 C8 C14 C18 C20 C21 C23 C26 C28 C29 C31 C32 C34 C92 C102 C159 C162 C178 C186-C189 C402 C404 C405 = 1C_0.01uFCapacitor16V10%0402
C105 C107 C110 C111 C365 = 1uFCapacitor10V10%0402
C108 = 2.2uFCapacitor35V20%smd0805: MfrNum: C2012X7R1V225M125AE
C54 C55 C62 C63 C123 C305 C306 C312 C313 C352 C359 C360 = 0.1uFCapacitor16V10%0402: MfrNum: C0402C104K4RACTU
C13 C22 C30 C364 = 1C_4.7uFCapacitor16V10%0603
J2 = Header10x2_CJTAG
J11 = Conn_14pin_0.5mm_FPC
R15 R254 R258 R499 = ZeroOhmResistor1_16W0402
R38 R84 R88 R262 R270 R272 R279 R286 R290 = 1R_33ohmResistor1_16W5%0402
R259 = 100ohm1_10W1%SMD0402
R6 R9 R19 R31 R257 R277 R355 R357 R509 R510 R536 R537 R539 R561 = 1R_10KOhmResistor1_16W0402
R33 R59-R62 R64 R66 R303 R461 R462 R479 R480 R512 R513 R541 R542 = 1R_4.7KOhmResistor1_16W0402
R498 = 1R_820kohm1_16W1%smd0402: DescriptiveText: Resistor 820kohm 1/16W 1% 0402
R503 R511 = 1R_100KOhmResistor1_16W0402
SW4 = SwitchDIPRotaries_smd
TP2 TP11 TP13 TP15 TP24 TP27 = 2H_TestPointThroughHole
U48 = PCA9536: MfrNum: PCA9536DGKR
U86 = SN74LVC1G04DCKR_SC70-5: Crtd /date: VASANTHA/170516; DescriptiveText: IC SINGLE INVERTER GATE SC70-5; Mfr: TEXAS INSTRUMENTS; Mistral part number: NSPN00381; Part_type: ICS\DIGITAL\GATES
U143 = TPS22945DCKR_SC70-5: Crtd /date: VASANTHA/170516; DescriptiveText: IC LOW INPUT VOLTAGE CURRENT LIMITED LOAD SWITCH SC70-5; Mfr: TEXAS INSTRUMENTS; Mistral part number: NSPN00385; Part_type: ICS\POWER\MISC
C4 C15 C60 C61 C169 C368 C369 C371 C373-C378 = 1C_0.1uFCapacitor16V10%0402: MfrNum: C0402C104K4RACTU
D2-D10 = 1F_LED_Green: MfrNum: 5988170107F
R243-R250 = 1R_330ohm1_16W5%smd0402
U3 = 1A_TPIC2810: MfrNum: TPIC2810DR
C117 C118 = 1C_18pFCapacitor16V10%0402: MfrNum: CGA2B2C0G1H180J050BA
C56 C57 C64 C65 C308 C309 C315 C316 C401 = 10uFCapacitor16V10%0805
C403 = 1C_22uFCapacitor16V10%0805
FB1 FB2 FB5 = 1L_FerriteBead_220ohm2A: MfrNum: MPZ1608S221ATA00
FB4 = 1L_FerBead_180ohm200mA
J1 = 2C_MicroUSBAB: MfrNum: ZX62-AB-5PA(31)
L21 = 1L_NFM21PC474_EMIFilter
R11 = 1R_220ohm1_10W1%smd0402
R18 = 1R_12Kohm1_16W1%SMD0402
R34 R256 R263 R271 R273 R276 R283 R287 R288 R291 R297 R301 R302 R304-R308 R310-R313 R421 R440 = 1R_ZeroOhmResistor1_16W0402
R278 = 1R_2.2KOhmResistor1_16W0402
R574 = 1R_1MOhmResistor1_16W0402
TP9 TP19 TP25 TP35 TP36 = 2H_Testpoint_SMD1mmCircle
U2 = 1A_TPD2E001DRL: MfrNum: TPD2E001DRLR
U25 = 1A_FT2232_2
U28 = 1A_93C56EEPROM2Kbit
U29 = 1A_SN74LVC2G07: MfrNum: SN74LVC2G07DCKR
U31 = 1A_SN74AVC2T244: MfrNum: SN74AVC2T244DQMR
U32 = 1A_SN74LVC1G00DCK: MfrNum: SN74LVC1G00DCKR
U34 = 1A_SN74AVC4T245
U153 = TLV1117-33CDCY_SOT223-4: IC LDO VOLTAGE REGULATOR SOT223-4; Crtd /date: VASANTHA/100316; DescriptiveText: IC LDO VOLTAGE REGULATOR SOT223-4; Manufacturer: TEXAS INSTRUMENTS; Mfr: TEXAS INSTRUMENTS; Mistral part number: NSPN00353; Part_type: ICS\POWER\VOLTAGE REGULATOR
U154 U156 = SN74AVC2T245RSWR_QFN10: Crtd /date: VASANTHA/170516; DescriptiveText: IC DUAL-BIT DUAL SUPPLY BUS TRANSCEIVER QFN10; Mfr: TEXAS INSTRUMENTS; Mistral part number: NSPN00389; Part_type: ICS\TELECOM\TRANSCEIVER
Y3 = 1Y_Crystal12MHzABM3
R100 R110 R370 R387 R568 R569 = 1KOhmResistor1_16W0402
U10-U13 U36 U37 U40 U41 = SN74CBTLV3257RGY: MfrNum: SN74CBTLV3257RGYR
J4 = High_Density_20x6_Conn_Female
C42 C73 C321 C386 C387 C406 C407 = 1C_0.1uFCapacitor50V10%0402: MfrNum: C1005X7R1H104K050BB
J7 = 2H_PCIe_Edge_Fingers_0
R85 R91 = 1R_150ohm1_16W1%SMD0402
R51 R89 = 1R_100ohm1_16W1%SMD0402
R366 = 1R_3.3Kohm1_16W5%smd0402
R526 R528 R540 = 1R_10KOhmResistor1_10W1%0402
U151 = SN74LVC1T45DBVR_SOT-23-6: Crtd /date: VASANTHA/170516; DescriptiveText: IC SINGLE-BIT DUAL-SUPPLY BUS TRANSCEIVER SOT-23; Mfr: TEXAS INSTRUMENTS; MfrNum: SN74LVC1T45DBVR; Mistral part number: NSPN00380; Part_type: ICS\DIGITAL\COMBINATIONAL
U155 = TCA9517DGKR_VSSOP8: Crtd /date: VASANTHA/170516; DescriptiveText: IC 2-CHANNEL I2C BUS REPEATER VSSOP8; Mfr: TEXAS INSTRUMENTS; Mistral part number: NSPN00384; Part_type: ICS\DIGITAL\BUSTRANSCEIVER
R78 R81 R358 R360-R364 = 1R_1KOhmResistor1_16W0402
U8 = DS90LV011A: DescriptiveText: LVDS Interface IC SGL HIGH SPD DIFF DRVR; Mfr: TI; MfrNum: DS90LV011ATMF/NOPB
C370 C372 C379 = 1C_0.01uFCapacitor16V10%0402: MfrNum: C0402C103K4RACTU
J14 = HEADER_5X1: Crtd /date: VASANTHA/170516; DescriptiveText: CON HDR 5X1 2.54MM PITCH ST TH; Mfr: MOLEX; MfrNum: 0022032051; Mistral part number: NSPN00391; Part_type: CONNECTOR\HEADER
J16 J17 = HEADER_2X1: Crtd /date: VASANTHA/170516; DescriptiveText: CON HDR 2X1 2.54MM PITCH ST TH; Mfr: MOLEX; MfrNum: 0022032021; Mistral part number: NSPN00390; Part_type: CONNECTOR\HEADER
R515 R516 R518 = RESISTOR-4TERM: RES 0.1E 1/2W 0.5% 4-TERM1206; Crtd /date: VASANTHA/210316; DescriptiveText: RES 0.1E 1/2W 0.5% 4-TERM1206; Manufacturer: OHMITE; Manufacturer Part Number: LVK12R100DER; Mfr: OHMITE; MfrNum: LVK12R100DER; Mistral part number: NSPN00350; Part_type: RESISTORS\FIXED
R517 = RESISTOR-4TERM: RES 0.01E 1/2W 0.5% 4-TERM1206; Crtd /date: VASANTHA/210316; DescriptiveText: RES 0.01E 1/2W 0.5% 4-TERM1206; Manufacturer: OHMITE; Manufacturer Part Number: LVK12R010DER; Mfr: OHMITE; MfrNum: LVK12R010DER; Mistral part number: NSPN00351; Part_type: RESISTORS\FIXED
U145-U148 = INA226AIDGS_MSOP10: Crtd /date: VASANTHA/170516; DescriptiveText: IC BI-DIRECTIONAL CURRENT MONITER MSOP10; Mfr: TEXAS INSTRUMENTS; Mistral part number: NSPN00382; Part_type: ICS\INTERFACE

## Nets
DGND: C3.2 C4.2 C5.2 C8.2 C13.1 C14.1 C15.2 C18.2 C20.2 C21.1 C22.1 C23.2 C26.1 C28.2 C29.2 C30.2 C31.2 C32.2 C34.1 C42.2 C54.2 C55.2 C56.2 C57.2 C62.2 C63.2 C64.2 C65.2 C73.2 C92.2 C102.2 C107.2 C108.2 C111.1 C117.2 C118.2 C123.2 C159.2 C162.2 C169.2 C178.1 C186.2 C187.2 C188.2 C189.2 C305.2 C306.2 C308.2 C309.2 C312.2 C313.2 C315.2 C316.2 C321.2 C352.2 C359.2 C360.2 C364.2 C365.2 C368.1 C370.2 C371.1 C372.1 C374.1 C376.2 C377.1 C379.2 C386.1 C387.2 C401.2 C402.2 C403.2 C404.2 C405.2 C406.1 C407.2 FB4.2 J1.5(GND) J2.4(TDIS) J2.8(GND) J2.10(GND) J2.12(GND) J2.16(GND) J4.4 J4.10 J4.30 J4.39 J4.43 J4.44 J4.57 J4.62 J4.75 J4.79 J4.92 J4.102 J4.108 J4.109 J4.110 J4.111 J4.112 J4.113 J4.114 J4.115 J4.116 J4.117 J4.118 J4.119 J4.120 J7.A4(GND6) J7.A12(GND7) J7.A15(GND8) J7.A18(GND9) J7.B4(GND1) J7.B7(GND2) J7.B13(GND3) J7.B16(GND4) J7.B18(GND5) J11.8 J14.3 L21.2(GND) R6.1(P1) R9.1(P1) R18.2(P2) R19.1(P1) R31.1(P1) R78.1(P1) R85.1(P1) R91.1(P1) R100.1(P1) R110.1(P1) R297.1(P1) R303.1(P1) R360.1(P1) R361.1(P1) R363.1(P1) R366.1 R370.1(P1) R387.1(P1) R461.1(P1) R462.1(P1) R479.1(P1) R480.1(P1) R498.2 R509.1(P1) R510.1(P1) R528.2 R537.2(P2) R561.2(P2) R568.1(P1) R569.1(P1) U2.4(GND) U3.8(~{G}) U3.16(GND) U8.2(GND) U10.8(GND) U10.17(EPAD) U11.8(GND) U11.17(EPAD) U12.8(GND) U12.17(EPAD) U13.8(GND) U13.17(EPAD) U25.1(GND.1) U25.5(GND.2) U25.10(AGND) U25.11(GND.3) U25.13(TEST) U25.15(GND.4) U25.25(GND.5) U25.35(GND.6) U25.47(GND.7) U25.51(GND.8) U28.5(VSS) U28.7(NC1) U29.2(GND) U29.3(2A) U31.5(GND) U32.3(GND) U34.2(1DIR) U34.3(2DIR) U34.8(GND) U34.9(GND) U36.8(GND) U36.17(EPAD) U37.8(GND) U37.17(EPAD) U40.8(GND) U40.17(EPAD) U41.8(GND) U41.17(EPAD) U48.4(GND) U86.3(GND) U143.2(GND) U145.1(A1) U145.7(GND) U146.1(A1) U146.2(A0) U146.7(GND) U147.1(A1) U147.7(GND) U148.2(A0) U148.7(GND) U151.2(GND) U153.1(ADJ/GND) U154.2(~{OE}) U154.3(GND) U155.4(GND) U156.3(GND) ; also on sheet 4 5 6 7 8 9 10 11 12 13 14 15 16 17 18 28 29
GNDUSBJ: FB4.1 J1.S1 J1.S2 J1.S3 J1.S4
V1_8FTDI: C8.1 C18.1 C29.1 C30.1 C32.1 U25.12(VCORE.1) U25.37(VCORE.2) U25.49(VREGOUT) U25.64(VCORE.3)
V3_3_PCIE: C386.2 C406.2 J7.A9(3.3V_2) J7.A10(3.3V_3) J7.B8(3.3V_1) R541.2(P2) R542.2(P2) U151.6(VCCB) U155.1(VCCA)
V3_3AUX_PCIE: J7.B10(3.3VAUX)
V3_3FTDI: C20.1 C23.1 C26.2 C28.1 C31.1 C34.2 C162.1 C169.1 C178.2 C187.1 C189.1 C402.1 C403.1 C404.1 FB1.2 FB2.2 R257.2(P2) R277.2(P2) U25.20(VCCIO.1) U25.31(VCCIO.2) U25.42(VCCIO.3) U25.50(VREGIN) U25.56(VCCIO.4) U28.6(NC2) U28.8(VCC) U29.5(VCC) U31.8(VCCB) U32.5(VCC) U34.16(VCCB) U153.2(OUTPUT1) U153.4(OUTPUT2) U154.6(VCCB) U156.6(VCCB)
V5_0: J4.3 J4.9 ; also on sheet 4 8
V12_0D: C73.1 C321.1 J7.A2(12V_4) J7.A3(12V_5) J7.B1(12V_1) J7.B2(12V_2) J7.B3(12V_3) ; also on sheet 28
VCC_LCD: C108.1 J11.1 TP2.1
VDD_0V9: C377.2 R517.3 ; also on sheet 4
VDD_0V9_K2G: R517.2 ; also on sheet 5
VDD_1V8: C368.2 R59.2(P2) R60.2(P2) R61.2(P2) R62.2(P2) R64.2(P2) R66.2(P2) R81.1(P1) R358.1(P1) R362.1(P1) R364.1(P1) R516.3 ; also on sheet 4 13 18
VDD_1V8_K2G: R516.2 ; also on sheet 5
VDD_3V3: C3.1 C4.1 C15.1 C42.1 C54.1 C55.1 C56.1 C57.1 C62.1 C63.1 C64.1 C65.1 C92.1 C107.1 C111.2 C159.1 C186.1 C188.1 C305.1 C306.1 C308.1 C309.1 C312.1 C313.1 C315.1 C316.1 C352.1 C359.1 C370.1 C371.2 C372.2 C376.1 C379.1 C387.1 C405.1 C407.1 J2.5(TVDD) J4.1 J4.2 J4.7 J4.8 J11.7 R243.2(P2) R244.2(P2) R245.2(P2) R246.2(P2) R247.2(P2) R248.2(P2) R249.2(P2) R250.2(P2) R355.2(P2) R357.2(P2) R503.2(P2) R511.1(P1) R512.2(P2) R513.2(P2) R515.3 R526.1 R536.1(P1) R539.2(P2) R540.1 SW4.C1 SW4.C2 U3.1(VCC) U8.1(VDD) U10.16(VCC) U11.16(VCC) U12.16(VCC) U13.16(VCC) U31.1(VCCA) U34.1(VCCA) U36.16(VCC) U37.16(VCC) U40.16(VCC) U41.16(VCC) U48.8(VCC) U86.5(VCC) U143.5(VIN) U145.6(VS+) U146.6(VS+) U147.2(A0) U147.6(VS+) U148.1(A1) U148.6(VS+) U151.1(VCCA) U154.7(VCCA) U155.8(VCCB) U156.7(VCCA) ; also on sheet 4 6 8 9 12 13 14 15 16 17 18
VDD_3V3_K2G: R515.2 ; also on sheet 5
VDDB: C360.1 C365.1 J11.10 U143.1(VOUT)
VDDS_DDR: C374.2 R518.3 ; also on sheet 4
VDDS_DDR_K2G: R518.2 ; also on sheet 4 5 7 10 11
C1N: C110.2 J11.11
C1P: C110.1 J11.12
C2N: C105.2 J11.13
C2P: C105.1 J11.14
DDR_VTT_SDn: U9.AA25(GPMC_DIR/GPIO0_25) ; also on sheet 4
EECS: U25.63(EECS) U28.1(CS)
EEDATA: R278.1(P1) U25.61(EEDATA) U28.3(DI)
EESK: U25.62(EESK) U28.2(CLK)
EMU0: J2.13(EMU0) R262.2
EMU2: R258.2(P2) ; also on sheet 9
EMU2R: J2.17(EMU2) R258.1(P1)
EMU3: R15.1(P1) ; also on sheet 9
EMU3R: J2.18(EMU3) R15.2(P2)
EMU4: R254.2(P2) ; also on sheet 9
EMU4R: J2.19(EMU4) R254.1(P1)
EMU_DETECT: J2.20(GND) R503.1(P1) U86.2(A)
EMU_RSTn: J2.15(SRST) R259.1(P1)
EMU_USB_DM: J1.2(DM) U2.5(IO2) U25.7(DM)
EMU_USB_DP: J1.3(DP) U2.3(IO1) U25.8(DP)
eQEP2_A: J4.33 ; also on sheet 9
eQEP2_B: J4.27 ; also on sheet 9
eQEP2_I: J4.21 ; also on sheet 9
eQEP2_S: J4.15 ; also on sheet 9
F_ADBUS0: R256.2(P2) U25.16(ADBUS0)
F_ADBUS1: R263.2(P2) U25.17(ADBUS1)
F_ADBUS2: R271.2(P2) U25.18(ADBUS2)
F_ADBUS3: R273.2(P2) U25.19(ADBUS3)
F_ADBUS4: R276.2(P2) U25.21(ADBUS4)
F_ADBUS5: R287.2(P2) U25.26(ACBUS0)
F_ADBUS6: R283.2(P2) U25.23(ADBUS6)
F_ADBUS7: R291.2(P2) U25.30(ACBUS4)
FT_SRESET: R287.1(P1) R303.2(P2) U32.1(A)
FT_SRESETB: R304.2(P2) U29.6(1Y)
FT_SRESETn: U29.1(1A) U32.4(Y)
FT_VBUS: R34.1(P1) U32.2(B)
FTDI_REF: R18.1(P1) U25.6(REF)
FTDI_VPHY: C21.2 C22.2 FB1.1 U25.4(VPHY)
FTDI_VPLL: C13.2 C14.2 FB2.1 U25.9(VPLL)
GB_ETH_RESETn: U9.AA20(GPMC_AD10/GPIO0_10) ; also on sheet 13
GPIO0_00: J4.36 U9.AC21(GPMC_AD0/GPIO0_00)
GPIO0_01: J4.42 U9.AE20(GPMC_AD1/GPIO0_01)
GPIO0_02: J4.48 U9.AD22(GPMC_AD2/GPIO0_02)
GPIO0_03: J4.54 U9.AD20(GPMC_AD3/GPIO0_03)
GPIO0_04: J4.60 U9.AE21(GPMC_AD4/GPIO0_04)
GPIO0_05: J4.66 U9.AE22(GPMC_AD5/GPIO0_05)
GPIO0_06: J4.72 U9.AC20(GPMC_AD6/GPIO0_06)
GPIO0_07: J4.78 U9.AD21(GPMC_AD7/GPIO0_07)
GPIO0_08: J4.84 U9.AE23(GPMC_AD8/GPIO0_08)
GPIO0_09: J4.90 U9.AB20(GPMC_AD9/GPIO0_09)
GPIO_PR0_MII0_RESETn: U9.AA24(GPMC_WAIT1/GPIO0_23) ; also on sheet 14
GPIO_PR0_MII1_RESETn: U9.AB24(GPMC_BEn1/GPIO0_21) ; also on sheet 15
GPIO_PR1_MII0_RESETn: U9.AC24(GPMC_BEn0_CLE/GPIO0_20) ; also on sheet 16
GPIO_PR1_MII1_RESETn: U9.W25(GPMC_WPn/GPIO0_24) ; also on sheet 17
I2C_SCL0: J4.50 ; also on sheet 6 8 13
I2C_SCL1: J11.5 U3.15(SCL) U48.6(SCL) U155.7(SCLB) ; also on sheet 6
I2C_SCL2: J16.1 ; also on sheet 6
I2C_SDA0: J4.56 ; also on sheet 6 8 13
I2C_SDA1: J11.4 U3.2(SDA) U48.7(SDA) U155.6(SDAB) ; also on sheet 6
I2C_SDA2: J17.1 ; also on sheet 6
IREF: J11.3 R498.1
JTAG_EMU0: R262.1 R307.1(P1) R355.1(P1) U9.M22(EMU00)
JTAG_EMU1: J2.14(EMU1) R302.1(P1) R357.1(P1) U9.L22(EMU01)
JTAG_OEn: R308.1(P1) U86.4(Y)
JTAG_TCK: R270.1 R272.1 R310.1(P1) U9.L3(TCK)
JTAG_TDI: R286.1 R311.1(P1) U9.L5(TDI)
JTAG_TDO: R279.1 R301.1(P1) U9.K5(TDO)
JTAG_TDO_B: R301.2(P2) U31.2(A1)
JTAG_TMS: R290.1 R312.1(P1) U9.K4(TMS)
JTAG_TRSTn: R38.1 R313.1(P1) U9.L4(TRSTn)
K2G_PCIE_RXn0: J7.B14(PETp0) U9.D1(PCIE_RXN0)
K2G_PCIE_RXp0: J7.B15(PETn0) U9.E1(PCIE_RXP0)
K2G_PCIE_TXn0: C60.1 U9.H1(PCIE_TXN0)
K2G_PCIE_TXp0: C61.1 U9.G1(PCIE_TXP0)
K2G_PCIECONN_TXn0: C60.2 J7.A17(PERn0)
K2G_PCIECONN_TXp0: C61.2 J7.A16(PERp0)
K2G_PRU0MII0_COL: U10.7(2A) ; also on sheet 14
K2G_PRU0MII0_CRS: U36.4(1A) ; also on sheet 14
K2G_PRU0MII0_MRCLK: U41.9(3A) ; also on sheet 14
K2G_PRU0MII0_RXD0: U36.9(3A) ; also on sheet 14
K2G_PRU0MII0_RXD1: U12.9(3A) ; also on sheet 14
K2G_PRU0MII0_RXD2: U41.7(2A) ; also on sheet 14
K2G_PRU0MII0_RXD3: U10.12(4A) ; also on sheet 14
K2G_PRU0MII0_RXDV: U10.4(1A) ; also on sheet 14
K2G_PRU0MII0_RXER: U10.9(3A) ; also on sheet 14
K2G_PRU0MII0_RXLINK: U12.12(4A) ; also on sheet 14
K2G_PRU0MII0_RXLINK_SW: U12.14(4B1) ; also on sheet 14
K2G_PRU0MII0_TXCLK: U36.7(2A) ; also on sheet 14
K2G_PRU0MII0_TXD0: U41.12(4A) ; also on sheet 14
K2G_PRU0MII0_TXD1: U36.12(4A) ; also on sheet 14
K2G_PRU0MII0_TXD2: U12.7(2A) ; also on sheet 14
K2G_PRU0MII0_TXD3: U12.4(1A) ; also on sheet 14
K2G_PRU0MII0_TXEN: U41.4(1A) ; also on sheet 14
K2G_PRU0MII1_COL: U13.12(4A) ; also on sheet 15
K2G_PRU0MII1_CRS: U13.4(1A) ; also on sheet 15
K2G_PRU0MII1_MRCLK: U40.7(2A) ; also on sheet 15
K2G_PRU0MII1_RXD0: U11.12(4A) ; also on sheet 15
K2G_PRU0MII1_RXD1: U37.4(1A) ; also on sheet 15
K2G_PRU0MII1_RXD2: U11.9(3A) ; also on sheet 15
K2G_PRU0MII1_RXD3: U11.4(1A) ; also on sheet 15
K2G_PRU0MII1_RXDV: U13.9(3A) ; also on sheet 15
K2G_PRU0MII1_RXER: U40.9(3A) ; also on sheet 15
K2G_PRU0MII1_RXLINK: U40.12(4A) ; also on sheet 15
K2G_PRU0MII1_RXLINK_SW: U40.14(4B1) ; also on sheet 15
K2G_PRU0MII1_TXCLK: U13.7(2A) ; also on sheet 15
K2G_PRU0MII1_TXD0: U37.9(3A) ; also on sheet 15
K2G_PRU0MII1_TXD1: U37.7(2A) ; also on sheet 15
K2G_PRU0MII1_TXD2: U11.7(2A) ; also on sheet 15
K2G_PRU0MII1_TXD3: U37.12(4A) ; also on sheet 15
K2G_PRU0MII1_TXEN: U40.4(1A) ; also on sheet 15
K2G_UART0_RXD: U9.T4(UART0_RXD) U154.9(A2)
K2G_UART0_TXD: U9.T1(UART0_TXD) U154.8(A1)
K2GIN_PCIE_REF_CLKN: R88.2 R89.1(P1) R91.2(P2) U9.F2(PCIE_CLK_N)
K2GIN_PCIE_REF_CLKP: R84.2 R85.2(P2) R89.2(P2) U9.G2(PCIE_CLK_P)
LCD_BST_CONV_CTL: R510.2(P2) U9.D21(UART2_TXD/GPIO1_53) U143.4(ON)
LED1: D2.1(Cathode) J4.5 U3.3(DRAIN0)
LED2: D3.1(Cathode) J4.11 U3.4(DRAIN1)
LED3: D4.1(Cathode) J4.18 U3.5(DRAIN2)
LED4: D5.1(Cathode) J4.24 U3.6(DRAIN3)
LED5: D6.1(Cathode) U3.11(DRAIN4)
LED6: D7.1(Cathode) U3.12(DRAIN5)
LED7: D8.1(Cathode) U3.13(DRAIN6)
LED8: D9.1(Cathode) U3.14(DRAIN7)
LED_1: U9.AD23(GPMC_AD11/GPIO0_11) ; also on sheet 8
LED_2: U9.AA21(GPMC_AD12/GPIO0_12) ; also on sheet 8
LED_3: U9.AB21(GPMC_AD13/GPIO0_13) ; also on sheet 8
LED_4: U9.AB22(GPMC_AD14/GPIO0_14) ; also on sheet 8
LED_5: U9.AA22(GPMC_AD15/GPIO0_15) ; also on sheet 8
LED_6: U9.AB23(GPMC_CLK/GPIO0_16) ; also on sheet 8
LED_7: U9.Y22(GPMC_WEn/GPIO0_19) ; also on sheet 8
LED_12: U9.P3(SPI2_SCSn0/GPIO0_101) ; also on sheet 8
LED_13: U9.P4(SPI2_SCSn1/GPIO0_102) ; also on sheet 8
MUX_MII_CTL_PRU0MII0: R568.2(P2) U9.U1(UART0_RTSn/GPIO0_107) U10.1(S) U12.1(S) U36.1(S) U41.1(S)
MUX_MII_CTL_PRU0MII1: R569.2(P2) U9.T2(UART0_CTSn/GPIO0_106) U11.1(S) U13.1(S) U37.1(S) U40.1(S)
OE_PRU0MII0_1: R100.2(P2) U10.15(OE#) U41.15(OE#) ; also on sheet 12
OE_PRU0MII0_2: R370.2(P2) U12.15(OE#) U36.15(OE#) ; also on sheet 12
OE_PRU0MII1_1: R110.2(P2) U9.R5(DCAN0_RX/GPIO1_57) U11.15(OE#) U13.15(OE#)
OE_PRU0MII1_2: R387.2(P2) U9.P5(DCAN0_TX/GPIO1_56) U37.15(OE#) U40.15(OE#)
OLED_RESETn: R499.2(P2) R509.2(P2) U9.E21(UART2_RXD/GPIO1_52)
PCIE_REFCLKN: J7.A14(REFCLK-) R88.1
PCIE_REFCLKP: J7.A13(REFCLK+) R84.1
PCIE_SMB_CLK: J7.B5(SMCLK) R542.1(P1) U155.2(SCLA)
PCIE_SMB_DATA: J7.B6(SMDAT) R541.1(P1) U155.3(SDAA)
PCIE_WAKEn_CONN: J7.B11(WAKEn) TP25.1
PERST: R526.2 U151.3(A) ; also on sheet 4
PERST_CON: R421.1(P1) U151.4(B)
PMBUS_SCL: J14.1 J16.2 R513.1(P1) U145.2(A0) U145.5(SCL) U146.5(SCL) U147.5(SCL) U148.5(SCL)
PMBUS_SDA: J14.2 J17.2 R512.1(P1) U145.4(SDA) U146.4(SDA) U147.4(SDA) U148.4(SDA)
PR0_ECAP0_ECAP_CAPIN_APWM_O: J4.104 ; also on sheet 13
PR0_EDC_LATCH0_IN: J4.85 U9.C5(PR0_PRU0_GPO18/PR0_EDC_LATCH0_IN)
PR0_EDC_LATCH1_IN: J4.91 U9.A9(PR0_PRU1_GPO18/PR0_EDC_LATCH1_IN)
PR0_EDC_SYNC0_OUT: J4.97 U9.A5(PR0_PRU0_GPO19/PR0_EDC_SYNC0_OUT)
PR0_EDC_SYNC1_OUT: J4.103 U9.B10(PR0_PRU1_GPO19/PR0_EDC_SYNC1_OUT)
PR0_EDIO_DATA0: J4.81 ; also on sheet 13
PR0_EDIO_DATA1: J4.87 ; also on sheet 13
PR0_EDIO_DATA2: J4.93 ; also on sheet 13
PR0_EDIO_DATA3: J4.99 ; also on sheet 13
PR0_EDIO_OUTVALID: J4.105 ; also on sheet 9
PR0_MII0_INTn: U9.W23(GPMC_CSn2/GPIO0_28) ; also on sheet 14
PR0_MII1_INTn: U9.Y25(GPMC_CSn3/GPIO0_29) ; also on sheet 15
PR0_PRU0_GPO7: J4.26 U9.D4(PR0_PRU0_GPO7/GPIO0_115)
PR0_PRU0_PRU_R30_OUT[0]: J4.16 U36.10(3B2)
PR0_PRU0_PRU_R30_OUT[1]: J4.22 U12.10(3B2)
PR0_PRU0_PRU_R30_OUT[2]: J4.28 U41.6(2B2)
PR0_PRU0_PRU_R30_OUT[3]: J4.34 U10.13(4B2)
PR0_PRU0_PRU_R30_OUT[4]: J4.40 U10.3(1B2)
PR0_PRU0_PRU_R30_OUT[5]: J4.46 U10.10(3B2)
PR0_PRU0_PRU_R30_OUT[6]: J4.52 U41.10(3B2)
PR0_PRU0_PRU_R30_OUT[8]: J4.58 U12.13(4B2)
PR0_PRU0_PRU_R30_OUT[9]: J4.88 U10.6(2B2)
PR0_PRU0_PRU_R30_OUT[10]: J4.94 U36.3(1B2)
PR0_PRU0_PRU_R30_OUT[11]: J4.64 U37.10(3B2)
PR0_PRU0_PRU_R30_OUT[12]: J4.70 U37.6(2B2)
PR0_PRU0_PRU_R30_OUT[13]: J4.76 U11.6(2B2)
PR0_PRU0_PRU_R30_OUT[14]: J4.82 U37.13(4B2)
PR0_PRU0_PRU_R30_OUT[15]: J4.100 U40.3(1B2)
PR0_PRU0_PRU_R30_OUT[16]: J4.106 U13.6(2B2)
PR0_PRU1_PRU_R30_OUT[0]: J4.17 U11.13(4B2)
PR0_PRU1_PRU_R30_OUT[1]: J4.23 U37.3(1B2)
PR0_PRU1_PRU_R30_OUT[2]: J4.29 U11.10(3B2)
PR0_PRU1_PRU_R30_OUT[3]: J4.35 U11.3(1B2)
PR0_PRU1_PRU_R30_OUT[4]: J4.41 U13.10(3B2)
PR0_PRU1_PRU_R30_OUT[5]: J4.47 U40.10(3B2)
PR0_PRU1_PRU_R30_OUT[6]: J4.53 U40.6(2B2)
PR0_PRU1_PRU_R30_OUT[7]: J4.38 U9.D8(PR0_PRU1_GPO7/GPIO0_135)
PR0_PRU1_PRU_R30_OUT[8]: J4.59 U40.13(4B2)
PR0_PRU1_PRU_R30_OUT[9]: J4.89 U13.13(4B2)
PR0_PRU1_PRU_R30_OUT[10]: J4.95 U13.3(1B2)
PR0_PRU1_PRU_R30_OUT[11]: J4.65 U41.13(4B2)
PR0_PRU1_PRU_R30_OUT[12]: J4.71 U36.13(4B2)
PR0_PRU1_PRU_R30_OUT[13]: J4.77 U12.6(2B2)
PR0_PRU1_PRU_R30_OUT[14]: J4.83 U12.3(1B2)
PR0_PRU1_PRU_R30_OUT[15]: J4.101 U41.3(1B2)
PR0_PRU1_PRU_R30_OUT[16]: J4.107 U36.6(2B2)
PR0_UART0RXD: J4.14 ; also on sheet 13
PR0_UART0TXD: J4.20 ; also on sheet 13
PR1_ECAP0_ECAP_CAPIN_APWM_O: J4.98 ; also on sheet 9
PR1_ECAP0_ECAP_SYNCIN: J4.80 ; also on sheet 9
PR1_ECAP0_ECAP_SYNCOUT: J4.86 ; also on sheet 9
PR1_EDC_LATCH0_IN: J4.45 U9.D12(PR1_PRU0_GPO18/PR1_EDC_LATCH0_IN)
PR1_EDC_LATCH1_IN: J4.51 U9.E17(PR1_PRU1_GPO18/PR1_EDC_LATCH1_IN)
PR1_EDC_SYNC0_OUT: J4.69 U9.D13(PR1_PRU0_GPO19/PR1_EDC_SYNC0_OUT)
PR1_EDC_SYNC1_OUT: J4.63 U9.E16(PR1_PRU1_GPO19/PR1_EDC_SYNC1_OUT)
PR1_MII0_INTn: U9.AC23(GPMC_ADVn_ALE/GPIO0_17) ; also on sheet 16
PR1_MII1_INTn: U9.Y24(GPMC_WAIT0/GPIO0_22) ; also on sheet 17
PR1_PRU0_GPO7: J4.96 U9.E12(PR1_PRU0_GPO7/GPIO1_13)
PR1_UART0RXD: J4.32 U9.C4(PR0_PRU0_GPO17/PR1_UART0_RXD)
PR1_UART0TXD: J4.68 U9.B9(PR0_PRU1_GPO17/PR1_UART0_TXD)
PRESENTn: J7.B17(PRSNT2#) R440.1(P1)
PRU0_MII0_COL: U10.5(2B1) ; also on sheet 14
PRU0_MII0_CRS: U36.2(1B1) ; also on sheet 14
PRU0_MII0_RXCLK: U41.11(3B1) ; also on sheet 14
PRU0_MII0_RXD0: U36.11(3B1) ; also on sheet 14
PRU0_MII0_RXD1: U12.11(3B1) ; also on sheet 14
PRU0_MII0_RXD2: U41.5(2B1) ; also on sheet 14
PRU0_MII0_RXD3: U10.14(4B1) ; also on sheet 14
PRU0_MII0_RXDV: U10.2(1B1) ; also on sheet 14
PRU0_MII0_RXERR: U10.11(3B1) ; also on sheet 14
PRU0_MII0_TXCLK: U36.5(2B1) ; also on sheet 14
PRU0_MII0_TXD0: U41.14(4B1) ; also on sheet 14
PRU0_MII0_TXD1: U36.14(4B1) ; also on sheet 14
PRU0_MII0_TXD2: U12.5(2B1) ; also on sheet 14
PRU0_MII0_TXD3: U12.2(1B1) ; also on sheet 14
PRU0_MII0_TXEN: U41.2(1B1) ; also on sheet 14
PRU0MII1_COL: U13.14(4B1) ; also on sheet 15
PRU0MII1_CRS: U13.2(1B1) ; also on sheet 15
PRU0MII1_RXCLK: U40.5(2B1) ; also on sheet 15
PRU0MII1_RXD0: U11.14(4B1) ; also on sheet 15
PRU0MII1_RXD1: U37.2(1B1) ; also on sheet 15
PRU0MII1_RXD2: U11.11(3B1) ; also on sheet 15
PRU0MII1_RXD3: U11.2(1B1) ; also on sheet 15
PRU0MII1_RXDV: U13.11(3B1) ; also on sheet 15
PRU0MII1_RXERR: U40.11(3B1) ; also on sheet 15
PRU0MII1_TXCLK: U13.5(2B1) ; also on sheet 15
PRU0MII1_TXD0: U37.11(3B1) ; also on sheet 15
PRU0MII1_TXD1: U37.5(2B1) ; also on sheet 15
PRU0MII1_TXD2: U11.5(2B1) ; also on sheet 15
PRU0MII1_TXD3: U37.14(4B1) ; also on sheet 15
PRU0MII1_TXEN: U40.2(1B1) ; also on sheet 15
RESn: J11.6 R499.1(P1)
RTCK: J2.9(TCKRTN) R272.2
SPI0_CLK: J4.13 U9.M2(SPI0_CLK)
SPI0_SCS0: J4.31 U9.M3(SPI0_SCSn0)
SPI0_SCS1: J4.37 U9.M4(SPI0_SCSn1)
SPI0_SIMO: J4.25 U9.N4(SPI0_SIMO)
SPI0_SOMI: J4.19 U9.M1(SPI0_SOMI)
SPI1_CLK: J4.49 U9.N2(SPI1_CLK)
SPI1_SCS0: J4.67 U9.P1(SPI1_SCSn0)
SPI1_SCS1: J4.73 U9.N3(SPI1_SCSn1)
SPI1_SIMO: J4.61 U9.P2(SPI1_SIMO)
SPI1_SOMI: J4.55 U9.N1(SPI1_SOMI)
SYS_RESETn: C123.1 R259.2(P2) ; also on sheet 6
SYS_WARMRESETn: R304.1(P1) ; also on sheet 6
SYSCLK: U8.5(TTL_IN) ; also on sheet 13
SYSCLKN: R51.2(P2) U8.3(OUT-) U9.AC25(SYSCLK_N)
SYSCLKP: R51.1(P1) U8.4(OUT+) U9.AD25(SYSCLK_P)
TCK_B: R310.2(P2) U34.4(1A1)
TCLK: J2.11(TCK) R270.2
TDI: J2.3(TDI) R286.2
TDI_B: R311.2(P2) U34.5(1A2)
TDO: J2.7(TDO) R279.2
TMS: J2.1(TMS) R290.2
TMS_B: R312.2(P2) U34.6(2A1)
TRST: R313.2(P2) U34.7(2A2)
TRSTN: J2.2(TRSTn) R38.2
UARTx_RXD: R305.1(P1) U154.4(B2)
UARTx_TXD: R306.1(P1) U154.5(B1)
USBJTAG_ENn: R308.2(P2) U31.4(~{OE}) U34.14(2~{OE}) U34.15(1~{OE}) U156.2(~{OE})
VCOMH: C364.1 J11.2
VMAIN: J4.6 J4.12 ; also on sheet 4 28
VUSB_FTDI: C102.1 C401.1 D10.2(Anode) FB5.2 L21.3(OUT) R33.2(P2) U153.3(INPUT)
VUSB_JTAG: C5.1 FB5.1 J1.1(VBUS) L21.1(IN) U2.1(VCC)
XTIN: C118.1 R574.2(P2) U25.2(XTIN) Y3.1
XTOUT: C117.1 R574.1(P1) U25.3(XTOUT) Y3.2
N29705372: R288.2(P2) U25.28(ACBUS2)
N29705374: R288.1(P1) U31.6(B2)
N29705378: R297.2(P2) U25.32(ACBUS5)
N29705384: R31.2(P2) R33.1(P1) R34.2(P2) U25.59(BCBUS7)
N29705440: R257.1(P1) U25.14(RESET#)
N29705493: D10.1(Cathode) R11.2
N29705528: R277.1(P1) R278.2(P2) U28.4(DO)
N29705585: TP9.1 U25.36(SUSPEND#)
N29705589: R11.1 U25.60(PWREN#)
N29705805: R256.1(P1) U34.13(1B1)
N29705822: R276.1(P1) U34.10(2B2)
N29705824: R273.1(P1) U34.11(2B1)
N29705826: R271.1(P1) U31.7(B1)
N29705828: R263.1(P1) U34.12(1B2)
N29706594: R305.2(P2) U25.38(BDBUS0)
N29706597: R306.2(P2) U25.39(BDBUS1)
N29706869: R283.1(P1) U156.5(B1)
N29706878: R291.1(P1) U156.4(B2)
N30607670: R462.2(P2) SW4.1(P0) U48.1(P0)
N30607672: R461.2(P2) SW4.2(P1) U48.2(P1)
N30607688: R480.2(P2) SW4.4(P2) U48.3(P2)
N30607690: R479.2(P2) SW4.8(P3) U48.5(P3)
N31012054: J7.A1(PRSNT1#) R440.2(P2)
N31012257: R366.2 U9.H7(PCIE_REFRES)
N31166417: R9.2(P2) U3.9(A0)
N31166424: R6.2(P2) U3.10(A1)
N31166431: R19.2(P2) U3.7(A2)
N31625725: J7.A11(PERSTn) R421.2(P2)
N31626220: TP35.1 U9.K1(OBSCLK_P)
N31626237: TP36.1 U9.L1(OBSCLK_N)
N31626244: R364.2(P2) U9.K21(CPTS_REFCLK_P)
N31626251: R361.2(P2) U9.L21(CPTS_REFCLK_N)
N31626744: R81.2(P2) U9.L24(MLBP_SIG_P)
N31626786: R78.2(P2) U9.M24(MLBP_SIG_N)
N31626788: R362.2(P2) U9.K23(MLBP_DAT_P)
N31626798: R363.2(P2) U9.K22(MLBP_DAT_N)
N31626800: R358.2(P2) U9.M23(MLBP_CLK_P)
N31626802: R360.2(P2) U9.L23(MLBP_CLK_N)
N33461643: R511.2(P2) U143.3(OC)
N33509145: C373.1 R515.4 U146.8(VBUS) U146.10(VIN+)
N33509178: C373.2 R515.1 U146.9(VIN-)
N33509182: C378.2 R517.1 U147.9(VIN-)
N33509202: C369.1 R516.4 U145.8(VBUS) U145.10(VIN+)
N33509208: C369.2 R516.1 U145.9(VIN-)
N33509212: C375.2 R518.1 U148.9(VIN-)
N33509214: C375.1 R518.4 U148.8(VBUS) U148.10(VIN+)
N33509389: C378.1 R517.4 U147.8(VBUS) U147.10(VIN+)
N33798475: R537.1(P1) U154.1(DIR2)
N33802977: R536.2(P2) U154.10(DIR1)
N33807565: R539.1(P1) U31.3(A2)
N33829757: R540.2 U155.5(EN)
N34178926: R528.1 U151.5(DIR)
N34231466: R561.1(P1) U156.1(DIR2) U156.10(DIR1)
N34232620: R307.2(P2) U156.8(A1)
N34232622: R302.2(P2) U156.9(A2)
N35161742: R66.1(P1) U9.Y1(RSV13)
N35161746: R64.1(P1) U9.AA1(RSV14)
N35161748: R61.1(P1) U9.AB1(RSV15)
N35161750: R62.1(P1) U9.AA2(RSV16)
N35161752: R60.1(P1) U9.AB2(RSV17)
N35161754: R59.1(P1) U9.AC1(RSV18)
N35163106: TP13.1 U9.W19(RSV4)
N35163109: TP11.1 U9.Y20(RSV3)
N35163315: TP24.1 U9.F18(RSV8)
N35163320: TP15.1 U9.H2(RSV9)
N35163328: TP27.1 U9.G3(RSV7)
N35163444: TP19.1 U9.D2(RSV5)
N35256457: D9.2(Anode) R243.1(P1)
N35345533: D3.2(Anode) R249.1(P1)
N35345534: D4.2(Anode) R248.1(P1)
N35345535: D5.2(Anode) R247.1(P1)
N35345536: D7.2(Anode) R245.1(P1)
N35345537: D8.2(Anode) R244.1(P1)
N35345538: D6.2(Anode) R246.1(P1)
N35345539: D2.2(Anode) R250.1(P1)

Not connected (* = marked no-connect by the designer): J1 4(ID)*; J2 6(NC)*; J4 74; J7 A5(JTAG_TCK)* A6(JTAG_TDI)* A7(JTAG_TDO)* A8(JTAG_TMS)* B9(JTAG_TRSTN)* B12(RSVD)*; J11 9*; J14 4* 5*; U2 2(NC)*; U9 A18(USB0_DP)* A19(USB0_ID)* A20(USB1_DM)* A21(USB1_VBUS)* AA18(RSV10)* AA19(RSV1)* AB19(RSV2)* AB25(GPMC_CSn0)* AC22(GPMC_OEn_Ren)* B15(PR1_PRU1_GPO7)* B18(USB0_DM)* B19(USB0_VBUS)* B20(USB1_DP)* B21(USB1_DRVVBUS)* C19(USB0_TXRTUNE_RKELVIN)* C20(USB1_XO)* C21(UART2_RTSn)* D19(USB0_XO)* D20(USB1_TXRTUNE_RKELVIN)* D22(UART2_CTSn)* E13(PR1_PRU0_GPO17)* E19(USB0_DRVVBUS)* E20(USB1_ID)* F16(PR1_PRU1_GPO17)* N5(OBSPLL_LOCK)* R2(SPI2_CLK)* R3(SPI2_SIMO)* R4(SPI2_SOMI)* T3(UART1_RXD)* T5(UART1_TXD)* U2(UART1_CTSn)* U4(UART1_RTSn)* W24(GPMC_CSn1)* Y14(RSV12)* Y19(RSV11)*; U25 22(ADBUS5)* 24(ADBUS7)* 27(ACBUS1)* 29(ACBUS3)* 33(ACBUS6)* 34(ACBUS7)* 40(BDBUS2)* 41(BDBUS3)* 43(BDBUS4)* 44(BDBUS5)* 45(BDBUS6)* 46(BDBUS7)* 48(BCBUS0)* 52(BCBUS1)* 53(BCBUS2)* 54(BCBUS3)* 55(BCBUS4)* 57(BCBUS5)* 58(BCBUS6)*; U29 4(2Y)*; U86 1(NC)*; U145 3(ALERT)*; U146 3(ALERT)*; U147 3(ALERT)*; U148 3(ALERT)*

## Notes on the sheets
sheet 19
- SMART REFLEX & MISC
- MONOCHROME LCD INTERFACE
- VCC Generated by internal DC/DC Circuit
- Power up VDDB (100ms
  Delay Recommended)
- JTAG CONNECTOR
- ROTARY SWITCH - INDUSTRIAL ETHERNET SLAVE ADDRESS SELECTOR
- I2C Address = 0x41h
sheet 20
- INDUSTRIAL OUTPUT LEDS
- I2C Address = 0x6xh
sheet 21
- USB JTAG
- USB CONN
sheet 22
- MUX/DEMUX 1
sheet 23
- MUX DEMUX 2
sheet 24
- EXPANSION CONNECTOR
- GPIO EXPANSION
- SPI0
- SPI1
sheet 25
- PCIe Edge Fingers
- For reducing routing complexity,
  Polarity has been swapped at
  connector side for RX signals
sheet 26
- GPIOS / UNUSED PINS
sheet 27
- INA DEVICES
- I2C ADDRESS: 0x41
- I2C ADDRESS: 0x40
- Note :- Put the Shut to J16 & J17 for connecting INA devices to the Processor
- I2C ADDRESS: 0x43
- I2C ADDRESS: 0x44
